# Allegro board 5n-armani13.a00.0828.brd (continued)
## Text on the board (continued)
BOTTOM: list("[Spacing] BOTTOM" "164.Shape to Route Keepin" "0 MIL [DEFAULT]" "0 MIL" "0.00 MIL" "DRC ERROR CLASS/BOTTOM" "[Shape] Route Keepin/All ((-191.01 273.9) (8699.38 4792.96))" "[Bottom Shape] GND ((-190.81 3053.41) (316.0 3564.87))" list(-170.750000 3410.250000) nil)@@@list("iris_chen" "2017/08/22 17:18:39" nil "P16C000357-PC" "5n-armani13.a00")@@@list("anson_lee" "2017/08/24 14:23:02" nil "P172000029-PC" "5n-armani13.a00.0824") | list("[Spacing] BOTTOM" "169.Shape to Route Keepin" "0 MIL [DEFAULT]" "0 MIL" "0.00 MIL" "DRC ERROR CLASS/BOTTOM" "[Shape] Route Keepin/All ((-191.01 273.9) (8699.38 4792.96))" "[Bottom Shape] GND ((-178.93 2335.01) (329.36 2652.0))" list(-106.990000 2480.120000) nil)@@@list("iris_chen" "2017/08/22 17:18:32" nil "P16C000357-PC" "5n-armani13.a00")@@@list("anson_lee" "2017/08/24 14:23:07" nil "P172000029-PC" "5n-armani13.a00.0824") | list("[Spacing] BOTTOM" "1.Shape to Route Keepout" "0 MIL [DEFAULT]" "0 MIL" "0.00 MIL" "DRC ERROR CLASS/BOTTOM" "[Shape] Route Keepout/Bottom ((-101.81 3966.17) (127.19 4181.63))" "[Bottom Shape] GND ((-191.01 273.9) (8699.38 4792.96))" list(-99.870000 3966.170000) nil)@@@list("iris_chen" "2017/08/24 17:08:49" nil "P16C000357-PC" "5n-armani13.a00")@@@list("jennifer_hsu" "2017/08/25 12:01:17" nil "p143000039-pc" "5n-armani13.a00") | list("[Spacing] BOTTOM" "3.Shape to Route Keepout" "0 MIL [DEFAULT]" "0 MIL" "0.00 MIL" "DRC ERROR CLASS/BOTTOM" "[Shape] Route Keepout/All ((-211.01 253.9) (8719.38 4812.96))" "[Bottom Shape] GND ((-90.47 1360.18) (215.46 1675.18))" list(-90.350000 1464.670000) nil)@@@list("iris_chen" "2017/08/22 17:18:35" nil "P16C000357-PC" "5n-armani13.a00")@@@list("anson_lee" "2017/08/24 14:34:02" nil "P172000029-PC" "5n-armani13.a00.0824") | list("[Spacing] BOTTOM" "2.Shape to Route Keepin" "0 MIL [DEFAULT]" "0 MIL" "0.00 MIL" "DRC ERROR CLASS/BOTTOM" "[Shape] Route Keepin/All ((-191.01 273.9) (8699.38 4792.96))" "[Bottom Shape] GND ((-90.47 1360.18) (215.46 1675.18))" list(-82.350000 1446.130000) nil)@@@list("iris_chen" "2017/08/22 17:18:34" nil "P16C000357-PC" "5n-armani13.a00")@@@list("anson_lee" "2017/08/24 14:34:01" nil "P172000029-PC" "5n-armani13.a00.0824") | list("[Spacing] BOTTOM" "179.Shape to Route Keepout" "0 MIL [DEFAULT]" "0 MIL" "0.00 MIL" "DRC ERROR CLASS/BOTTOM" "[Shape] Route Keepout/Bottom ((-109.54 1350.18) (225.46 1685.18))" "[Bottom Shape] GND ((-82.35 273.9) (8493.57 1710.0))" list(-82.350000 1426.200000) nil)@@@list("iris_chen" "2017/08/22 17:18:36" nil "P16C000357-PC" "5n-armani13.a00")@@@nil | list("[Spacing] BOTTOM" "167.Shape to Route Keepout" "0 MIL [DEFAULT]" "0 MIL" "0.00 MIL" "DRC ERROR CLASS/BOTTOM" "[Shape] Route Keepout/All ((-211.01 253.9) (8719.38 4812.96))" "[Bottom Shape] GND ((-24.57 3163.49) (207.43 3395.49))" list(-24.570000 3185.200000) nil)@@@list("iris_chen" "2017/08/22 17:18:33" nil "P16C000357-PC" "5n-armani13.a00")@@@list("anson_lee" "2017/08/24 14:23:05" nil "P172000029-PC" "5n-armani13.a00.0824") | list("[Spacing] BOTTOM" "168.Shape to Route Keepout" "0 MIL [DEFAULT]" "0 MIL" "0.00 MIL" "DRC ERROR CLASS/BOTTOM" "[Shape] Route Keepout/All ((-237.5 2495.83) (182.17 3240.31))" "[Bottom Shape] GND ((-24.57 3163.49) (207.43 3395.49))" list(-24.570000 3185.190000) nil)@@@list("iris_chen" "2017/08/22 17:18:33" nil "P16C000357-PC" "5n-armani13.a00")@@@list("anson_lee" "2017/08/24 14:23:06" nil "P172000029-PC" "5n-armani13.a00.0824") | list("[Spacing] BOTTOM" "181.Shape to Route Keepin" "0 MIL [DEFAULT]" "0 MIL" "0.00 MIL" "DRC ERROR CLASS/BOTTOM" "[Shape] Route Keepin/All ((-191.01 273.9) (8699.38 4792.96))" "[Bottom Shape] AGND ((-21.02 1889.86) (162.01 1960.27))" list(-2.240000 1932.020000) nil)@@@list("iris_chen" "2017/08/22 17:18:41" nil "P16C000357-PC" "5n-armani13.a00")@@@list("anson_lee" "2017/08/24 14:23:49" nil "P172000029-PC" "5n-armani13.a00.0824") | list("[Spacing] BOTTOM" "182.Thru Pin to Thru Pin" "5 MIL [(12)]" "4 MIL" "1.00 MIL" "DRC ERROR CLASS/BOTTOM" "[ThruPin] TX2N_P1_C (<uTiL>cId4355<uTiL>.B3) (12.89 3746.02)" "[ThruPin] TX2P_P1_C (<uTiL>cId4355<uTiL>.B2) (12.89 3777.52)" list(12.890000 3759.770000) nil)@@@list("iris_chen" "2017/08/22 17:18:41" nil "P16C000357-PC" "5n-armani13.a00")@@@list("anson_lee" "2017/08/24 14:23:50" nil "P172000029-PC" "5n-armani13.a00.0824") | list("[Spacing] BOTTOM" "165.Thru Pin to Thru Pin" "5 MIL [(12)]" "4 MIL" "1.00 MIL" "DRC ERROR CLASS/BOTTOM" "[ThruPin] RX1N_P1 (<uTiL>cId4355<uTiL>.B10) (12.89 3612.16)" "[ThruPin] RX1P_P1 (<uTiL>cId4355<uTiL>.B11) (12.89 3580.66)" list(12.890000 3598.410000) nil)@@@list("iris_chen" "2017/08/22 17:18:37" nil "P16C000357-PC" "5n-armani13.a00")@@@list("anson_lee" "2017/08/24 14:23:03" nil "P172000029-PC" "5n-armani13.a00.0824") | list("[Spacing] BOTTOM" "180.Thru Pin to Thru Pin" "5 MIL [(15)]" "4 MIL" "1.00 MIL" "DRC ERROR CLASS/BOTTOM" "[ThruPin] DN2 (<uTiL>cId4355<uTiL>.B7) (48.32 3663.34)" "[ThruPin] DP2 (<uTiL>cId4355<uTiL>.B6) (48.32 3694.84)" list(48.320000 3677.090000) nil)@@@list("iris_chen" "2017/08/22 17:18:38" nil "P16C000357-PC" "5n-armani13.a00")@@@list("anson_lee" "2017/08/24 14:23:48" nil "P172000029-PC" "5n-armani13.a00.0824") | list("[Spacing] BOTTOM" "179.Shape to Route Keepin" "0 MIL [DEFAULT]" "0 MIL" "0.00 MIL" "DRC ERROR CLASS/BOTTOM" "[Shape] Route Keepin/All ((-191.01 273.9) (8699.38 4792.96))" "[Bottom Shape] AGND ((26.54 2279.82) (160.9 2337.32))" list(49.770000 2282.580000) nil)@@@list("iris_chen" "2017/08/22 17:18:31" nil "P16C000357-PC" "5n-armani13.a00")@@@list("anson_lee" "2017/08/24 14:23:47" nil "P172000029-PC" "5n-armani13.a00.0824") | list("[Spacing] BOTTOM" "171.Shape to Route Keepout" "0 MIL [DEFAULT]" "0 MIL" "0.00 MIL" "DRC ERROR CLASS/BOTTOM" "[Shape] Route Keepout/Bottom ((-101.81 3966.17) (127.19 4181.63))" "[Bottom Shape] GND ((-191.01 273.9) (8699.38 4792.96))" list(64.170000 3966.170000) nil)@@@list("iris_chen" "2017/08/22 17:18:37" nil "P16C000357-PC" "5n-armani13.a00")@@@list("anson_lee" "2017/08/24 14:23:10" nil "P172000029-PC" "5n-armani13.a00.0824") | list("[Spacing] BOTTOM" "172.Drill Hole to Pin" "8 MIL [DEFAULT]" "7.99 MIL" "0.01 MIL" "DRC ERROR CLASS/BOTTOM" "[ThruPin] Dummy (<uTiL>cId4355<uTiL>.24) (93.01 3814.92)" "[SmdPin] GND (<uTiL>cId4355<uTiL>.A12) (90.65 3787.36)" list(98.230000 3800.860000) nil)@@@list("iris_chen" "2017/08/22 17:18:37" nil "P16C000357-PC" "5n-armani13.a00")@@@list("anson_lee" "2017/08/24 14:23:11" nil "P172000029-PC" "5n-armani13.a00.0824") | list("[Spacing] BOTTOM" "185.Drill Hole to Pin" "8 MIL [DEFAULT]" "7.99 MIL" "0.01 MIL" "DRC ERROR CLASS/BOTTOM" "[ThruPin] Dummy (<uTiL>cId4355<uTiL>.23) (93.01 3543.26)" "[SmdPin] GND (<uTiL>cId4355<uTiL>.A1) (90.65 3570.82)" list(98.230000 3557.320000) nil)@@@list("iris_chen" "2017/08/22 17:18:30" nil "P16C000357-PC" "5n-armani13.a00")@@@list("anson_lee" "2017/08/24 14:23:55" nil "P172000029-PC" "5n-armani13.a00.0824") | list("[Spacing] BOTTOM" "166.Shape to Route Keepin" "0 MIL [DEFAULT]" "0 MIL" "0.00 MIL" "DRC ERROR CLASS/BOTTOM" "[Shape] Route Keepin/All ((-191.01 273.9) (8699.38 4792.96))" "[Bottom Shape] GND ((-24.57 3163.49) (207.43 3395.49))" list(188.890000 3163.490000) nil)@@@list("iris_chen" "2017/08/22 17:18:32" nil "P16C000357-PC" "5n-armani13.a00")@@@list("anson_lee" "2017/08/24 14:23:04" nil "P172000029-PC" "5n-armani13.a00.0824") | list("[Physical] BOTTOM" "261.Pad/Pad Direct Connect" "NOT_ALLOWED [85OHM(DP_4|4.3|4|5/4/5/200)]" "ALL_ALLOWED" "" "DRC ERROR CLASS/BOTTOM" "[SmdPin] DN1 (<uTiL>cId1333<uTiL>.3) (354.17 3552.53)" "[SmdPin] DN1 (<uTiL>cId2437<uTiL>.4) (353.0 3544.0)" list(353.000000 3544.000000) nil)@@@list("iris_chen" "2017/08/22 17:19:52" nil "P16C000357-PC" "5n-armani13.a00")@@@list("anson_lee" "2017/08/24 14:24:52" nil "P172000029-PC" "5n-armani13.a00.0824") | list("[Physical] BOTTOM" "363.Pad/Pad Direct Connect" "NOT_ALLOWED [85OHM(DP_4|4.3|4|5/4/5/200)]" "ALL_ALLOWED" "" "DRC ERROR CLASS/BOTTOM" "[SmdPin] DN1_MUX (<uTiL>cId1333<uTiL>.4) (354.17 3493.47)" "[SmdPin] DN1_MUX (<uTiL>cId2437<uTiL>.3) (353.0 3502.0)" list(353.000000 3502.000000) nil)@@@list("iris_chen" "2017/08/22 17:19:39" nil "P16C000357-PC" "5n-armani13.a00")@@@list("anson_lee" "2017/08/24 14:26:01" nil "P172000029-PC" "5n-armani13.a00.0824") | list("[Physical] BOTTOM" "386.Pad/Pad Direct Connect" "NOT_ALLOWED [85OHM(DP_4|4.3|4|5/4/5/200)]" "ALL_ALLOWED" "" "DRC ERROR CLASS/BOTTOM" "[SmdPin] DP1_MUX (<uTiL>cId2437<uTiL>.1) (377.0 3502.0)" "[SmdPin] DP1_MUX (<uTiL>cId1333<uTiL>.1) (375.83 3493.47)" list(375.830000 3493.470000) nil)@@@list("iris_chen" "2017/08/22 17:21:12" nil "P16C000357-PC" "5n-armani13.a00")@@@list("anson_lee" "2017/08/24 14:26:15" nil "P172000029-PC" "5n-armani13.a00.0824") | list("[Physical] BOTTOM" "273.Pad/Pad Direct Connect" "NOT_ALLOWED [85OHM(DP_4|4.3|4|5/4/5/200)]" "ALL_ALLOWED" "" "DRC ERROR CLASS/BOTTOM" "[SmdPin] DP1 (<uTiL>cId1333<uTiL>.2) (375.83 3552.53)" "[SmdPin] DP1 (<uTiL>cId2437<uTiL>.2) (377.0 3544.0)" list(377.000000 3544.000000) nil)@@@list("iris_chen" "2017/08/22 17:19:12" nil "P16C000357-PC" "5n-armani13.a00")@@@list("anson_lee" "2017/08/24 14:24:59" nil "P172000029-PC" "5n-armani13.a00.0824") | list("[Physical] BOTTOM" "337.Pad/Pad Direct Connect" "NOT_ALLOWED [(GND_20)]" "ALL_ALLOWED" "" "DRC ERROR CLASS/BOTTOM" "[SmdPin] GND (<uTiL>cId30<uTiL>.49) (460.0 1405.0)" "[ThruPin] GND (<uTiL>cId30<uTiL>.50) (380.5 1484.5)" list(380.500000 1484.500000) nil)@@@list("iris_chen" "2017/08/22 17:21:11" nil "P16C000357-PC" "5n-armani13.a00")@@@list("anson_lee" "2017/08/24 14:25:43" nil "P172000029-PC" "5n-armani13.a00.0824") | list("[Physical] BOTTOM" "332.Pad/Pad Direct Connect" "NOT_ALLOWED [(GND_20)]" "ALL_ALLOWED" "" "DRC ERROR CLASS/BOTTOM" "[SmdPin] GND (<uTiL>cId30<uTiL>.49) (460.0 1405.0)" "[ThruPin] GND (<uTiL>cId30<uTiL>.51) (380.5 1405.0)" list(380.500000 1405.000000) nil)@@@list("iris_chen" "2017/08/22 17:19:50" nil "P16C000357-PC" "5n-armani13.a00")@@@list("anson_lee" "2017/08/24 14:25:40" nil "P172000029-PC" "5n-armani13.a00.0824") | list("[Physical] BOTTOM" "331.Pad/Pad Direct Connect" "NOT_ALLOWED [(GND_20)]" "ALL_ALLOWED" "" "DRC ERROR CLASS/BOTTOM" "[SmdPin] GND (<uTiL>cId30<uTiL>.49) (460.0 1405.0)" "[ThruPin] GND (<uTiL>cId30<uTiL>.52) (380.5 1325.5)" list(380.500000 1325.500000) nil)@@@list("iris_chen" "2017/08/22 17:19:50" nil "P16C000357-PC" "5n-armani13.a00")@@@list("anson_lee" "2017/08/24 14:25:39" nil "P172000029-PC" "5n-armani13.a00.0824") | list("[Physical] BOTTOM" "257.Pad/Pad Direct Connect" "NOT_ALLOWED [85OHM(DP_4|4.3|4|5/4/5/200)]" "ALL_ALLOWED" "" "DRC ERROR CLASS/BOTTOM" "[SmdPin] HDMI_TMDS_CLK_N (<uTiL>cId4643<uTiL>.2) (430.0 2901.0)" "[SmdPin] HDMI_TMDS_CLK_N (<uTiL>cId2614<uTiL>.4) (420.47 2899.83)" list(420.470000 2899.830000) nil)@@@list("iris_chen" "2017/08/22 17:19:14" nil "P16C000357-PC" "5n-armani13.a00")@@@list("anson_lee" "2017/08/24 14:24:50" nil "P172000029-PC" "5n-armani13.a00.0824") | list("[Physical] BOTTOM" "265.Pad/Pad Direct Connect" "NOT_ALLOWED [85OHM(DP_4|4.3|4|5/4/5/200)]" "ALL_ALLOWED" "" "DRC ERROR CLASS/BOTTOM" "[SmdPin] HDMI_TMDS_CLK_P (<uTiL>cId4643<uTiL>.4) (430.0 2877.0)" "[SmdPin] HDMI_TMDS_CLK_P (<uTiL>cId2614<uTiL>.1) (420.47 2878.17)" list(420.470000 2878.170000) nil)@@@list("iris_chen" "2017/08/22 17:19:12" nil "P16C000357-PC" "5n-armani13.a00")@@@list("anson_lee" "2017/08/24 14:24:54" nil "P172000029-PC" "5n-armani13.a00.0824") | list("[Physical] BOTTOM" "254.Pad/Pad Direct Connect" "NOT_ALLOWED [85OHM(DP_4|4.3|4|5/4/5/200)]" "ALL_ALLOWED" "" "DRC ERROR CLASS/BOTTOM" "[SmdPin] HDMI_TMDS_DATA1_N (<uTiL>cId4645<uTiL>.2) (429.0 2727.0)" "[SmdPin] HDMI_TMDS_DATA1_N (<uTiL>cId2616<uTiL>.4) (420.47 2726.83)" list(420.470000 2726.830000) nil)@@@list("iris_chen" "2017/08/22 17:19:36" nil "P16C000357-PC" "5n-armani13.a00")@@@list("anson_lee" "2017/08/24 14:24:48" nil "P172000029-PC" "5n-armani13.a00.0824") | list("[Physical] BOTTOM" "382.Pad/Pad Direct Connect" "NOT_ALLOWED [85OHM(DP_4|4.3|4|5/4/5/200)]" "ALL_ALLOWED" "" "DRC ERROR CLASS/BOTTOM" "[SmdPin] HDMI_TMDS_DATA2_N (<uTiL>cId4644<uTiL>.2) (429.0 2637.0)" "[SmdPin] HDMI_TMDS_DATA2_N (<uTiL>cId2615<uTiL>.4) (420.47 2635.83)" list(420.470000 2635.830000) nil)@@@list("iris_chen" "2017/08/22 17:19:13" nil "P16C000357-PC" "5n-armani13.a00")@@@list("anson_lee" "2017/08/24 14:26:13" nil "P172000029-PC" "5n-armani13.a00.0824") | list("[Physical] BOTTOM" "268.Pad/Pad Direct Connect" "NOT_ALLOWED [85OHM(DP_4|4.3|4|5/4/5/200)]" "ALL_ALLOWED" "" "DRC ERROR CLASS/BOTTOM" "[SmdPin] HDMI_TMDS_DATA0_N (<uTiL>cId4646<uTiL>.2) (430.0 2811.0)" "[SmdPin] HDMI_TMDS_DATA0_N (<uTiL>cId2617<uTiL>.4) (421.47 2809.83)" list(421.470000 2809.830000) nil)@@@list("iris_chen" "2017/08/22 17:19:56" nil "P16C000357-PC" "5n-armani13.a00")@@@list("anson_lee" "2017/08/24 14:24:56" nil "P172000029-PC" "5n-armani13.a00.0824") | list("[Physical] BOTTOM" "253.Pad/Pad Direct Connect" "NOT_ALLOWED [85OHM(DP_4|4.3|4|5/4/5/200)]" "ALL_ALLOWED" "" "DRC ERROR CLASS/BOTTOM" "[SmdPin] HDMI_TMDS_DATA1_P (<uTiL>cId2616<uTiL>.1) (420.47 2705.17)" "[SmdPin] HDMI_TMDS_DATA1_P (<uTiL>cId4645<uTiL>.4) (429.0 2703.0)" list(429.000000 2703.000000) nil)@@@list("iris_chen" "2017/08/22 17:21:12" nil "P16C000357-PC" "5n-armani13.a00")@@@list("anson_lee" "2017/08/24 14:24:47" nil "P172000029-PC" "5n-armani13.a00.0824") | list("[Physical] BOTTOM" "272.Pad/Pad Direct Connect" "NOT_ALLOWED [85OHM(DP_4|4.3|4|5/4/5/200)]" "ALL_ALLOWED" "" "DRC ERROR CLASS/BOTTOM" "[SmdPin] HDMI_TMDS_DATA2_P (<uTiL>cId2615<uTiL>.1) (420.47 2614.17)" "[SmdPin] HDMI_TMDS_DATA2_P (<uTiL>cId4644<uTiL>.4) (429.0 2613.0)" list(429.000000 2613.000000) nil)@@@list("iris_chen" "2017/08/22 17:19:36" nil "P16C000357-PC" "5n-armani13.a00")@@@list("anson_lee" "2017/08/24 14:24:59" nil "P172000029-PC" "5n-armani13.a00.0824") | list("[Physical] BOTTOM" "252.Pad/Pad Direct Connect" "NOT_ALLOWED [85OHM(DP_4|4.3|4|5/4/5/200)]" "ALL_ALLOWED" "" "DRC ERROR CLASS/BOTTOM" "[SmdPin] HDMI_TMDS_DATA0_P (<uTiL>cId2617<uTiL>.1) (421.47 2788.17)" "[SmdPin] HDMI_TMDS_DATA0_P (<uTiL>cId4646<uTiL>.4) (430.0 2787.0)" list(430.000000 2787.000000) nil)@@@list("iris_chen" "2017/08/22 17:19:45" nil "P16C000357-PC" "5n-armani13.a00")@@@list("anson_lee" "2017/08/24 14:24:46" nil "P172000029-PC" "5n-armani13.a00.0824") | list("[Physical] BOTTOM" "388.Pad/Pad Direct Connect" "NOT_ALLOWED [DEFAULT]" "ALL_ALLOWED" "" "DRC ERROR CLASS/BOTTOM" "[ThruPin] PRO_THM (<uTiL>cId6387<uTiL>.19) (455.47 3890.81)" "[SmdPin] PRO_THM (<uTiL>cId6387<uTiL>.18) (485.0 3851.44)" list(455.470000 3890.810000) nil)@@@list("iris_chen" "2017/08/22 17:19:25" nil "P16C000357-PC" "5n-armani13.a00")@@@list("anson_lee" "2017/08/24 14:26:16" nil "P172000029-PC" "5n-armani13.a00.0824") | list("[Physical] BOTTOM" "394.Pad/Pad Direct Connect" "NOT_ALLOWED [DEFAULT]" "ALL_ALLOWED" "" "DRC ERROR CLASS/BOTTOM" "[ThruPin] PRO_THM (<uTiL>cId6387<uTiL>.20) (455.47 3851.44)" "[SmdPin] PRO_THM (<uTiL>cId6387<uTiL>.18) (485.0 3851.44)" list(455.470000 3851.440000) nil)@@@list("iris_chen" "2017/08/22 17:21:09" nil "P16C000357-PC" "5n-armani13.a00")@@@list("anson_lee" "2017/08/24 14:26:21" nil "P172000029-PC" "5n-armani13.a00.0824") | list("[Physical] BOTTOM" "393.Pad/Pad Direct Connect" "NOT_ALLOWED [DEFAULT]" "ALL_ALLOWED" "" "DRC ERROR CLASS/BOTTOM" "[ThruPin] PRO_THM (<uTiL>cId6387<uTiL>.21) (455.47 3812.07)" "[SmdPin] PRO_THM (<uTiL>cId6387<uTiL>.18) (485.0 3851.44)" list(455.470000 3812.070000) nil)@@@list("iris_chen" "2017/08/22 17:19:26" nil "P16C000357-PC" "5n-armani13.a00")@@@list("anson_lee" "2017/08/24 14:26:20" nil "P172000029-PC" "5n-armani13.a00.0824") | list("[Physical] BOTTOM" "283.Pad/Pad Direct Connect" "NOT_ALLOWED [(GND_20)]" "ALL_ALLOWED" "" "DRC ERROR CLASS/BOTTOM" "[SmdPin] GND (<uTiL>cId30<uTiL>.49) (460.0 1405.0)" "[ThruPin] GND (<uTiL>cId30<uTiL>.53) (460.0 1484.5)" list(460.000000 1484.500000) nil)@@@list("iris_chen" "2017/08/22 17:19:51" nil "P16C000357-PC" "5n-armani13.a00")@@@list("anson_lee" "2017/08/24 14:25:05" nil "P172000029-PC" "5n-armani13.a00.0824") | list("[Physical] BOTTOM" "333.Pad/Pad Direct Connect" "NOT_ALLOWED [(GND_20)]" "ALL_ALLOWED" "" "DRC ERROR CLASS/BOTTOM" "[SmdPin] GND (<uTiL>cId30<uTiL>.49) (460.0 1405.0)" "[ThruPin] GND (<uTiL>cId30<uTiL>.54) (460.0 1405.0)" list(460.000000 1405.000000) nil)@@@list("iris_chen" "2017/08/22 17:19:49" nil "P16C000357-PC" "5n-armani13.a00")@@@list("anson_lee" "2017/08/24 14:25:40" nil "P172000029-PC" "5n-armani13.a00.0824") | list("[Physical] BOTTOM" "334.Pad/Pad Direct Connect" "NOT_ALLOWED [(GND_20)]" "ALL_ALLOWED" "" "DRC ERROR CLASS/BOTTOM" "[SmdPin] GND (<uTiL>cId30<uTiL>.49) (460.0 1405.0)" "[ThruPin] GND (<uTiL>cId30<uTiL>.55) (460.0 1325.5)" list(460.000000 1325.500000) nil)@@@list("iris_chen" "2017/08/22 17:19:49" nil "P16C000357-PC" "5n-armani13.a00")@@@list("anson_lee" "2017/08/24 14:25:41" nil "P172000029-PC" "5n-armani13.a00.0824") | list("[Physical] BOTTOM" "349.Pad/Pad Direct Connect" "NOT_ALLOWED [(GND_20)]" "ALL_ALLOWED" "" "DRC ERROR CLASS/BOTTOM" "[SmdPin] GND (<uTiL>cId2509<uTiL>.21) (485.0 3419.0)" "[ThruPin] GND (<uTiL>cId2509<uTiL>.25) (465.31 3438.69)" list(465.310000 3438.690000) nil)@@@list("iris_chen" "2017/08/22 17:19:46" nil "P16C000357-PC" "5n-armani13.a00")@@@list("anson_lee" "2017/08/24 14:25:52" nil "P172000029-PC" "5n-armani13.a00.0824") | list("[Physical] BOTTOM" "348.Pad/Pad Direct Connect" "NOT_ALLOWED [(GND_20)]" "ALL_ALLOWED" "" "DRC ERROR CLASS/BOTTOM" "[SmdPin] GND (<uTiL>cId2509<uTiL>.21) (485.0 3419.0)" "[ThruPin] GND (<uTiL>cId2509<uTiL>.22) (465.31 3399.31)" list(465.310000 3399.310000) nil)@@@list("iris_chen" "2017/08/22 17:19:24" nil "P16C000357-PC" "5n-armani13.a00")@@@list("anson_lee" "2017/08/24 14:25:51" nil "P172000029-PC" "5n-armani13.a00.0824") | list("[Physical] BOTTOM" "258.Pad/Pad Direct Connect" "NOT_ALLOWED [85OHM(DP_4|4.3|4|5/4/5/200)]" "ALL_ALLOWED" "" "DRC ERROR CLASS/BOTTOM" "[SmdPin] HDMI_TXP1_SNK (<uTiL>cId2616<uTiL>.2) (479.53 2705.17)" "[SmdPin] HDMI_TXP1_SNK (<uTiL>cId4645<uTiL>.3) (471.0 2703.0)" list(471.000000 2703.000000) nil)@@@list("iris_chen" "2017/08/22 17:19:56" nil "P16C000357-PC" "5n-armani13.a00")@@@list("anson_lee" "2017/08/24 14:24:50" nil "P172000029-PC" "5n-armani13.a00.0824") | list("[Physical] BOTTOM" "278.Pad/Pad Direct Connect" "NOT_ALLOWED [85OHM(DP_4|4.3|4|5/4/5/200)]" "ALL_ALLOWED" "" "DRC ERROR CLASS/BOTTOM" "[SmdPin] HDMI_TXN2_SNK (<uTiL>cId2615<uTiL>.3) (479.53 2635.83)" "[SmdPin] HDMI_TXN2_SNK (<uTiL>cId4644<uTiL>.1) (471.0 2637.0)" list(471.000000 2637.000000) nil)@@@list("iris_chen" "2017/08/22 17:19:57" nil "P16C000357-PC" "5n-armani13.a00")@@@list("anson_lee" "2017/08/24 14:25:02" nil "P172000029-PC" "5n-armani13.a00.0824") | list("[Physical] BOTTOM" "361.Pad/Pad Direct Connect" "NOT_ALLOWED [85OHM(DP_4|4.3|4|5/4/5/200)]" "ALL_ALLOWED" "" "DRC ERROR CLASS/BOTTOM" "[SmdPin] HDMI_CLKN_SNK (<uTiL>cId2614<uTiL>.3) (479.53 2899.83)" "[SmdPin] HDMI_CLKN_SNK (<uTiL>cId4643<uTiL>.1) (472.0 2901.0)" list(472.000000 2901.000000) nil)@@@list("iris_chen" "2017/08/22 17:21:19" nil "P16C000357-PC" "5n-armani13.a00")@@@list("anson_lee" "2017/08/24 14:25:59" nil "P172000029-PC" "5n-armani13.a00.0824") | list("[Physical] BOTTOM" "362.Pad/Pad Direct Connect" "NOT_ALLOWED [85OHM(DP_4|4.3|4|5/4/5/200)]" "ALL_ALLOWED" "" "DRC ERROR CLASS/BOTTOM" "[SmdPin] HDMI_TXN0_SNK (<uTiL>cId2617<uTiL>.3) (480.53 2809.83)" "[SmdPin] HDMI_TXN0_SNK (<uTiL>cId4646<uTiL>.1) (472.0 2811.0)" list(472.000000 2811.000000) nil)@@@list("iris_chen" "2017/08/22 17:21:19" nil "P16C000357-PC" "5n-armani13.a00")@@@list("anson_lee" "2017/08/24 14:26:00" nil "P172000029-PC" "5n-armani13.a00.0824") | list("[Physical] BOTTOM" "383.Pad/Pad Direct Connect" "NOT_ALLOWED [85OHM(DP_4|4.3|4|5/4/5/200)]" "ALL_ALLOWED" "" "DRC ERROR CLASS/BOTTOM" "[SmdPin] HDMI_CLKP_SNK (<uTiL>cId4643<uTiL>.3) (472.0 2877.0)" "[SmdPin] HDMI_CLKP_SNK (<uTiL>cId2614<uTiL>.2) (479.53 2878.17)" list(479.530000 2878.170000) nil)@@@list("iris_chen" "2017/08/22 17:19:51" nil "P16C000357-PC" "5n-armani13.a00")@@@list("anson_lee" "2017/08/24 14:26:13" nil "P172000029-PC" "5n-armani13.a00.0824") | list("[Physical] BOTTOM" "259.Pad/Pad Direct Connect" "NOT_ALLOWED [85OHM(DP_4|4.3|4|5/4/5/200)]" "ALL_ALLOWED" "" "DRC ERROR CLASS/BOTTOM" "[SmdPin] HDMI_TXN1_SNK (<uTiL>cId4645<uTiL>.1) (471.0 2727.0)" "[SmdPin] HDMI_TXN1_SNK (<uTiL>cId2616<uTiL>.3) (479.53 2726.83)" list(479.530000 2726.830000) nil)@@@list("iris_chen" "2017/08/22 17:19:28" nil "P16C000357-PC" "5n-armani13.a00")@@@list("anson_lee" "2017/08/24 14:24:51" nil "P172000029-PC" "5n-armani13.a00.0824") | list("[Physical] BOTTOM" "269.Pad/Pad Direct Connect" "NOT_ALLOWED [85OHM(DP_4|4.3|4|5/4/5/200)]" "ALL_ALLOWED" "" "DRC ERROR CLASS/BOTTOM" "[SmdPin] HDMI_TXP2_SNK (<uTiL>cId4644<uTiL>.3) (471.0 2613.0)" "[SmdPin] HDMI_TXP2_SNK (<uTiL>cId2615<uTiL>.2) (479.53 2614.17)" list(479.530000 2614.170000) nil)@@@list("iris_chen" "2017/08/22 17:19:52" nil "P16C000357-PC" "5n-armani13.a00")@@@list("anson_lee" "2017/08/24 14:24:57" nil "P172000029-PC" "5n-armani13.a00.0824") | list("[Physical] BOTTOM" "255.Pad/Pad Direct Connect" "NOT_ALLOWED [85OHM(DP_4|4.3|4|5/4/5/200)]" "ALL_ALLOWED" "" "DRC ERROR CLASS/BOTTOM" "[SmdPin] HDMI_TXP0_SNK (<uTiL>cId4646<uTiL>.3) (472.0 2787.0)" "[SmdPin] HDMI_TXP0_SNK (<uTiL>cId2617<uTiL>.2) (480.53 2788.17)" list(480.530000 2788.170000) nil)@@@list("iris_chen" "2017/08/22 17:19:27" nil "P16C000357-PC" "5n-armani13.a00")@@@list("anson_lee" "2017/08/24 14:24:48" nil "P172000029-PC" "5n-armani13.a00.0824") | list("[Physical] BOTTOM" "392.Pad/Pad Direct Connect" "NOT_ALLOWED [DEFAULT]" "ALL_ALLOWED" "" "DRC ERROR CLASS/BOTTOM" "[ThruPin] PRO_THM (<uTiL>cId6387<uTiL>.22) (485.0 3871.13)" "[SmdPin] PRO_THM (<uTiL>cId6387<uTiL>.18) (485.0 3851.44)" list(485.000000 3871.130000) nil)@@@list("iris_chen" "2017/08/22 17:19:36" nil "P16C000357-PC" "5n-armani13.a00")@@@list("anson_lee" "2017/08/24 14:26:19" nil "P172000029-PC" "5n-armani13.a00.0824") | list("[Physical] BOTTOM" "391.Pad/Pad Direct Connect" "NOT_ALLOWED [DEFAULT]" "ALL_ALLOWED" "" "DRC ERROR CLASS/BOTTOM" "[ThruPin] PRO_THM (<uTiL>cId6387<uTiL>.23) (485.0 3831.76)" "[SmdPin] PRO_THM (<uTiL>cId6387<uTiL>.18) (485.0 3851.44)" list(485.000000 3831.760000) nil)@@@list("iris_chen" "2017/08/22 17:19:46" nil "P16C000357-PC" "5n-armani13.a00")@@@list("anson_lee" "2017/08/24 14:26:18" nil "P172000029-PC" "5n-armani13.a00.0824") | list("[Physical] BOTTOM" "345.Pad/Pad Direct Connect" "NOT_ALLOWED [(GND_20)]" "ALL_ALLOWED" "" "DRC ERROR CLASS/BOTTOM" "[SmdPin] GND (<uTiL>cId2509<uTiL>.21) (485.0 3419.0)" "[ThruPin] GND (<uTiL>cId2509<uTiL>.24) (485.0 3419.0)" list(485.000000 3419.000000) nil)@@@list("iris_chen" "2017/08/22 17:19:24" nil "P16C000357-PC" "5n-armani13.a00")@@@list("anson_lee" "2017/08/24 14:25:48" nil "P172000029-PC" "5n-armani13.a00.0824") | list("[Physical] BOTTOM" "346.Pad/Pad Direct Connect" "NOT_ALLOWED [(GND_20)]" "ALL_ALLOWED" "" "DRC ERROR CLASS/BOTTOM" "[SmdPin] GND (<uTiL>cId2509<uTiL>.21) (485.0 3419.0)" "[ThruPin] GND (<uTiL>cId2509<uTiL>.26) (504.69 3438.69)" list(504.690000 3438.690000) nil)@@@list("iris_chen" "2017/08/22 17:19:37" nil "P16C000357-PC" "5n-armani13.a00")@@@list("anson_lee" "2017/08/24 14:25:49" nil "P172000029-PC" "5n-armani13.a00.0824") | list("[Physical] BOTTOM" "282.Pad/Pad Direct Connect" "NOT_ALLOWED [(GND_20)]" "ALL_ALLOWED" "" "DRC ERROR CLASS/BOTTOM" "[SmdPin] GND (<uTiL>cId2509<uTiL>.21) (485.0 3419.0)" "[ThruPin] GND (<uTiL>cId2509<uTiL>.23) (504.69 3399.31)" list(504.690000 3399.310000) nil)@@@list("iris_chen" "2017/08/22 17:21:10" nil "P16C000357-PC" "5n-armani13.a00")@@@list("anson_lee" "2017/08/24 14:25:04" nil "P172000029-PC" "5n-armani13.a00.0824") | list("[Physical] BOTTOM" "387.Pad/Pad Direct Connect" "NOT_ALLOWED [DEFAULT]" "ALL_ALLOWED" "" "DRC ERROR CLASS/BOTTOM" "[ThruPin] PRO_THM (<uTiL>cId6387<uTiL>.24) (514.53 3890.81)" "[SmdPin] PRO_THM (<uTiL>cId6387<uTiL>.18) (485.0 3851.44)" list(514.530000 3890.810000) nil)@@@list("iris_chen" "2017/08/22 17:21:09" nil "P16C000357-PC" "5n-armani13.a00")@@@list("anson_lee" "2017/08/24 14:26:16" nil "P172000029-PC" "5n-armani13.a00.0824") | list("[Physical] BOTTOM" "390.Pad/Pad Direct Connect" "NOT_ALLOWED [DEFAULT]" "ALL_ALLOWED" "" "DRC ERROR CLASS/BOTTOM" "[ThruPin] PRO_THM (<uTiL>cId6387<uTiL>.25) (514.53 3851.44)" "[SmdPin] PRO_THM (<uTiL>cId6387<uTiL>.18) (485.0 3851.44)" list(514.530000 3851.440000) nil)@@@list("iris_chen" "2017/08/22 17:19:26" nil "P16C000357-PC" "5n-armani13.a00")@@@list("anson_lee" "2017/08/24 14:26:18" nil "P172000029-PC" "5n-armani13.a00.0824") | list("[Physical] BOTTOM" "389.Pad/Pad Direct Connect" "NOT_ALLOWED [DEFAULT]" "ALL_ALLOWED" "" "DRC ERROR CLASS/BOTTOM" "[ThruPin] PRO_THM (<uTiL>cId6387<uTiL>.26) (514.53 3812.07)" "[SmdPin] PRO_THM (<uTiL>cId6387<uTiL>.18) (485.0 3851.44)" list(514.530000 3812.070000) nil)@@@list("iris_chen" "2017/08/22 17:19:25" nil "P16C000357-PC" "5n-armani13.a00")@@@list("anson_lee" "2017/08/24 14:26:17" nil "P172000029-PC" "5n-armani13.a00.0824") | list("[Physical] BOTTOM" "335.Pad/Pad Direct Connect" "NOT_ALLOWED [(GND_20)]" "ALL_ALLOWED" "" "DRC ERROR CLASS/BOTTOM" "[SmdPin] GND (<uTiL>cId30<uTiL>.49) (460.0 1405.0)" "[ThruPin] GND (<uTiL>cId30<uTiL>.56) (539.5 1484.5)" list(539.500000 1484.500000) nil)@@@list("iris_chen" "2017/08/22 17:19:48" nil "P16C000357-PC" "5n-armani13.a00")@@@list("anson_lee" "2017/08/24 14:25:42" nil "P172000029-PC" "5n-armani13.a00.0824") | list("[Physical] BOTTOM" "352.Pad/Pad Direct Connect" "NOT_ALLOWED [(GND_20)]" "ALL_ALLOWED" "" "DRC ERROR CLASS/BOTTOM" "[SmdPin] GND (<uTiL>cId30<uTiL>.49) (460.0 1405.0)" "[ThruPin] GND (<uTiL>cId30<uTiL>.57) (539.5 1405.0)" list(539.500000 1405.000000) nil)@@@list("iris_chen" "2017/08/22 17:19:48" nil "P16C000357-PC" "5n-armani13.a00")@@@list("anson_lee" "2017/08/24 14:25:54" nil "P172000029-PC" "5n-armani13.a00.0824") | list("[Physical] BOTTOM" "336.Pad/Pad Direct Connect" "NOT_ALLOWED [(GND_20)]" "ALL_ALLOWED" "" "DRC ERROR CLASS/BOTTOM" "[SmdPin] GND (<uTiL>cId30<uTiL>.49) (460.0 1405.0)" "[ThruPin] GND (<uTiL>cId30<uTiL>.58) (539.5 1325.5)" list(539.500000 1325.500000) nil)@@@list("iris_chen" "2017/08/22 17:19:47" nil "P16C000357-PC" "5n-armani13.a00")@@@list("anson_lee" "2017/08/24 14:25:42" nil "P172000029-PC" "5n-armani13.a00.0824") | list("[Physical] BOTTOM" "291.Pad/Pad Direct Connect" "NOT_ALLOWED [(GND_20)]" "ALL_ALLOWED" "" "DRC ERROR CLASS/BOTTOM" "[SmdPin] GND (<uTiL>cId2761<uTiL>.11) (1556.0 870.0)" "[ThruPin] GND (<uTiL>cId2761<uTiL>.12) (1535.0 910.0)" list(1535.000000 910.000000) nil)@@@list("iris_chen" "2017/08/22 17:21:16" nil "P16C000357-PC" "5n-armani13.a00")@@@list("anson_lee" "2017/08/24 14:25:11" nil "P172000029-PC" "5n-armani13.a00.0824") | list("[Physical] BOTTOM" "289.Pad/Pad Direct Connect" "NOT_ALLOWED [(GND_20)]" "ALL_ALLOWED" "" "DRC ERROR CLASS/BOTTOM" "[ThruPin] GND (<uTiL>cId2761<uTiL>.13) (1535.0 830.0)" "[SmdPin] GND (<uTiL>cId2761<uTiL>.11) (1556.0 870.0)" list(1535.000000 830.000000) nil)@@@list("iris_chen" "2017/08/22 17:21:17" nil "P16C000357-PC" "5n-armani13.a00")@@@list("anson_lee" "2017/08/24 14:25:10" nil "P172000029-PC" "5n-armani13.a00.0824") | list("[Physical] BOTTOM" "292.Pad/Pad Direct Connect" "NOT_ALLOWED [(GND_20)]" "ALL_ALLOWED" "" "DRC ERROR CLASS/BOTTOM" "[SmdPin] GND (<uTiL>cId2761<uTiL>.11) (1556.0 870.0)" "[ThruPin] GND (<uTiL>cId2761<uTiL>.14) (1577.0 910.0)" list(1577.000000 910.000000) nil)@@@list("iris_chen" "2017/08/22 17:21:15" nil "P16C000357-PC" "5n-armani13.a00")@@@list("anson_lee" "2017/08/24 14:25:12" nil "P172000029-PC" "5n-armani13.a00.0824") | list("[Physical] BOTTOM" "290.Pad/Pad Direct Connect" "NOT_ALLOWED [(GND_20)]" "ALL_ALLOWED" "" "DRC ERROR CLASS/BOTTOM" "[SmdPin] GND (<uTiL>cId2761<uTiL>.11) (1556.0 870.0)" "[ThruPin] GND (<uTiL>cId2761<uTiL>.15) (1577.0 830.0)" list(1577.000000 830.000000) nil)@@@list("iris_chen" "2017/08/22 17:21:16" nil "P16C000357-PC" "5n-armani13.a00")@@@list("anson_lee" "2017/08/24 14:25:10" nil "P172000029-PC" "5n-armani13.a00.0824") | list("[Physical] BOTTOM" "250.Pad/Pad Direct Connect" "NOT_ALLOWED [85OHM(DP_4|4.3|4|5/4/5/200)]" "ALL_ALLOWED" "" "DRC ERROR CLASS/BOTTOM" "[SmdPin] USBN5_CAM (<uTiL>cId3444<uTiL>.2) (1859.47 4143.83)" "[SmdPin] USBN5_CAM (<uTiL>cId3529<uTiL>.3) (1868.0 4145.0)" list(1868.000000 4145.000000) nil)@@@list("iris_chen" "2017/08/22 17:21:24" nil "P16C000357-PC" "5n-armani13.a00")@@@list("anson_lee" "2017/08/24 14:24:45" nil "P172000029-PC" "5n-armani13.a00.0824") | list("[Physical] BOTTOM" "384.Pad/Pad Direct Connect" "NOT_ALLOWED [85OHM(DP_4|4.3|4|5/4/5/200)]" "ALL_ALLOWED" "" "DRC ERROR CLASS/BOTTOM" "[SmdPin] USBP5_CAM (<uTiL>cId3444<uTiL>.3) (1859.47 4122.17)" "[SmdPin] USBP5_CAM (<uTiL>cId3529<uTiL>.1) (1868.0 4121.0)" list(1868.000000 4121.000000) nil)@@@list("iris_chen" "2017/08/22 17:19:13" nil "P16C000357-PC" "5n-armani13.a00")@@@list("anson_lee" "2017/08/24 14:26:14" nil "P172000029-PC" "5n-armani13.a00.0824") | list("[Physical] BOTTOM" "385.Pad/Pad Direct Connect" "NOT_ALLOWED [85OHM(DP_4|4.3|4|5/4/5/200)]" "ALL_ALLOWED" "" "DRC ERROR CLASS/BOTTOM" "[SmdPin] USBP5+_CAM (<uTiL>cId3444<uTiL>.4) (1918.53 4122.17)" "[SmdPin] USBP5+_CAM (<uTiL>cId3529<uTiL>.2) (1910.0 4121.0)" list(1910.000000 4121.000000) nil)@@@list("iris_chen" "2017/08/22 17:21:24" nil "P16C000357-PC" "5n-armani13.a00")@@@list("anson_lee" "2017/08/24 14:26:15" nil "P172000029-PC" "5n-armani13.a00.0824") | list("[Physical] BOTTOM" "248.Pad/Pad Direct Connect" "NOT_ALLOWED [85OHM(DP_4|4.3|4|5/4/5/200)]" "ALL_ALLOWED" "" "DRC ERROR CLASS/BOTTOM" "[SmdPin] USBP5-_CAM (<uTiL>cId3529<uTiL>.4) (1910.0 4145.0)" "[SmdPin] USBP5-_CAM (<uTiL>cId3444<uTiL>.1) (1918.53 4143.83)" list(1918.530000 4143.830000) nil)@@@list("iris_chen" "2017/08/22 17:21:11" nil "P16C000357-PC" "5n-armani13.a00")@@@list("anson_lee" "2017/08/24 14:24:44" nil "P172000029-PC" "5n-armani13.a00.0824") | list("[Physical] BOTTOM" "270.Pad/Pad Direct Connect" "NOT_ALLOWED [DEFAULT]" "ALL_ALLOWED" "" "DRC ERROR CLASS/BOTTOM" "[SmdPin] +1P2V_DUAL_FB_VOUT_R_A (<uTiL>cId1150<uTiL>.2) (3549.0 4431.0)" "[SmdPin] +1P2V_DUAL_FB_VOUT_R_A (<uTiL>cId1170<uTiL>.1) (3513.46 4431.0)" list(3549.000000 4431.000000) nil)@@@list("iris_chen" "2017/08/22 17:19:58" nil "P16C000357-PC" "5n-armani13.a00")@@@list("anson_lee" "2017/08/24 14:24:57" nil "P172000029-PC" "5n-armani13.a00.0824") | list("[Physical] BOTTOM" "274.Pad/Pad Direct Connect" "NOT_ALLOWED [(PWR_20)]" "ALL_ALLOWED" "" "DRC ERROR CLASS/BOTTOM" "[SmdPin] +1P8VSB_OUT (<uTiL>cId1220<uTiL>.1) (3699.5 4650.94)" "[SmdPin] +1P8VSB_OUT (<uTiL>cId2794<uTiL>.2) (3717.0 4651.0)" list(3717.000000 4651.000000) nil)@@@list("iris_chen" "2017/08/22 17:19:31" nil "P16C000357-PC" "5n-armani13.a00")@@@list("anson_lee" "2017/08/24 14:25:00" nil "P172000029-PC" "5n-armani13.a00.0824") | list("[Spacing] BOTTOM" "183.Shape to Route Keepin" "0 MIL [DEFAULT]" "0 MIL" "0.00 MIL" "DRC ERROR CLASS/BOTTOM" "[Shape] Route Keepin/All ((-191.01 273.9) (8699.38 4792.96))" "[Bottom Shape] GND ((-82.35 273.9) (8493.57 1710.0))" list(3884.420000 504.590000) nil)@@@list("iris_chen" "2017/08/22 17:18:35" nil "P16C000357-PC" "5n-armani13.a00")@@@list("anson_lee" "2017/08/24 14:23:51" nil "P172000029-PC" "5n-armani13.a00.0824") | list("[Physical] BOTTOM" "293.Pad/Pad Direct Connect" "NOT_ALLOWED [(GND_20)]" "ALL_ALLOWED" "" "DRC ERROR CLASS/BOTTOM" "[ThruPin] GND (<uTiL>cId521<uTiL>.15) (4045.0 4696.0)" "[SmdPin] GND (<uTiL>cId521<uTiL>.11) (4066.0 4656.0)" list(4045.000000 4696.000000) nil)@@@list("iris_chen" "2017/08/22 17:19:40" nil "P16C000357-PC" "5n-armani13.a00")@@@list("anson_lee" "2017/08/24 14:25:12" nil "P172000029-PC" "5n-armani13.a00.0824") | list("[Physical] BOTTOM" "359.Pad/Pad Direct Connect" "NOT_ALLOWED [(GND_20)]" "ALL_ALLOWED" "" "DRC ERROR CLASS/BOTTOM" "[SmdPin] GND (<uTiL>cId521<uTiL>.11) (4066.0 4656.0)" "[ThruPin] GND (<uTiL>cId521<uTiL>.14) (4045.0 4616.0)" list(4045.000000 4616.000000) nil)@@@list("iris_chen" "2017/08/22 17:21:17" nil "P16C000357-PC" "5n-armani13.a00")@@@list("anson_lee" "2017/08/24 14:25:58" nil "P172000029-PC" "5n-armani13.a00.0824") | list("[Physical] BOTTOM" "294.Pad/Pad Direct Connect" "NOT_ALLOWED [(GND_20)]" "ALL_ALLOWED" "" "DRC ERROR CLASS/BOTTOM" "[SmdPin] GND (<uTiL>cId521<uTiL>.11) (4066.0 4656.0)" "[ThruPin] GND (<uTiL>cId521<uTiL>.13) (4087.0 4696.0)" list(4087.000000 4696.000000) nil)@@@list("iris_chen" "2017/08/22 17:19:27" nil "P16C000357-PC" "5n-armani13.a00")@@@list("anson_lee" "2017/08/24 14:25:13" nil "P172000029-PC" "5n-armani13.a00.0824") | list("[Physical] BOTTOM" "295.Pad/Pad Direct Connect" "NOT_ALLOWED [(GND_20)]" "ALL_ALLOWED" "" "DRC ERROR CLASS/BOTTOM" "[SmdPin] GND (<uTiL>cId521<uTiL>.11) (4066.0 4656.0)" "[ThruPin] GND (<uTiL>cId521<uTiL>.12) (4087.0 4616.0)" list(4087.000000 4616.000000) nil)@@@list("iris_chen" "2017/08/22 17:19:17" nil "P16C000357-PC" "5n-armani13.a00")@@@list("anson_lee" "2017/08/24 14:25:14" nil "P172000029-PC" "5n-armani13.a00.0824") | list("[Physical] BOTTOM" "298.Pad/Pad Direct Connect" "NOT_ALLOWED [(GND_20)]" "ALL_ALLOWED" "" "DRC ERROR CLASS/BOTTOM" "[SmdPin] GND (<uTiL>cId5906<uTiL>.41) (4225.0 4215.0)" "[ThruPin] GND (<uTiL>cId5906<uTiL>.43) (4168.0 4272.0)" list(4168.000000 4272.000000) nil)@@@list("iris_chen" "2017/08/22 17:19:41" nil "P16C000357-PC" "5n-armani13.a00")@@@list("anson_lee" "2017/08/24 14:25:16" nil "P172000029-PC" "5n-armani13.a00.0824") | list("[Physical] BOTTOM" "296.Pad/Pad Direct Connect" "NOT_ALLOWED [(GND_20)]" "ALL_ALLOWED" "" "DRC ERROR CLASS/BOTTOM" "[ThruPin] GND (<uTiL>cId5906<uTiL>.45) (4168.0 4158.0)" "[SmdPin] GND (<uTiL>cId5906<uTiL>.41) (4225.0 4215.0)" list(4168.000000 4158.000000) nil)@@@list("iris_chen" "2017/08/22 17:21:18" nil "P16C000357-PC" "5n-armani13.a00")@@@list("anson_lee" "2017/08/24 14:25:14" nil "P172000029-PC" "5n-armani13.a00.0824") | list("[Physical] BOTTOM" "360.Pad/Pad Direct Connect" "NOT_ALLOWED [(GND_20)]" "ALL_ALLOWED" "" "DRC ERROR CLASS/BOTTOM" "[SmdPin] GND (<uTiL>cId5906<uTiL>.41) (4225.0 4215.0)" "[ThruPin] GND (<uTiL>cId5906<uTiL>.42) (4282.0 4272.0)" list(4282.000000 4272.000000) nil)@@@list("iris_chen" "2017/08/22 17:19:55" nil "P16C000357-PC" "5n-armani13.a00")@@@list("anson_lee" "2017/08/24 14:25:59" nil "P172000029-PC" "5n-armani13.a00.0824") | list("[Physical] BOTTOM" "297.Pad/Pad Direct Connect" "NOT_ALLOWED [(GND_20)]" "ALL_ALLOWED" "" "DRC ERROR CLASS/BOTTOM" "[SmdPin] GND (<uTiL>cId5906<uTiL>.41) (4225.0 4215.0)" "[ThruPin] GND (<uTiL>cId5906<uTiL>.44) (4282.0 4158.0)" list(4282.000000 4158.000000) nil)@@@list("iris_chen" "2017/08/22 17:19:17" nil "P16C000357-PC" "5n-armani13.a00")@@@list("anson_lee" "2017/08/24 14:25:15" nil "P172000029-PC" "5n-armani13.a00.0824") | list("[Physical] BOTTOM" "324.Pad/Pad Direct Connect" "NOT_ALLOWED [(GND_20)]" "ALL_ALLOWED" "" "DRC ERROR CLASS/BOTTOM" "[SmdPin] GND (<uTiL>cId5764<uTiL>.9) (4674.63 4525.0)" "[ThruPin] GND (<uTiL>cId5764<uTiL>.13) (4634.46 4602.76)" list(4634.460000 4602.760000) nil)@@@list("iris_chen" "2017/08/22 17:19:32" nil "P16C000357-PC" "5n-armani13.a00")@@@list("anson_lee" "2017/08/24 14:25:34" nil "P172000029-PC" "5n-armani13.a00.0824") | list("[Physical] BOTTOM" "287.Pad/Pad Direct Connect" "NOT_ALLOWED [(GND_20)]" "ALL_ALLOWED" "" "DRC ERROR CLASS/BOTTOM" "[SmdPin] GND (<uTiL>cId5764<uTiL>.9) (4674.63 4525.0)" "[ThruPin] GND (<uTiL>cId5764<uTiL>.16) (4634.46 4542.62)" list(4634.460000 4542.620000) nil)@@@list("iris_chen" "2017/08/22 17:19:16" nil "P16C000357-PC" "5n-armani13.a00")@@@list("anson_lee" "2017/08/24 14:25:07" nil "P172000029-PC" "5n-armani13.a00.0824") | list("[Physical] BOTTOM" "285.Pad/Pad Direct Connect" "NOT_ALLOWED [(GND_20)]" "ALL_ALLOWED" "" "DRC ERROR CLASS/BOTTOM" "[ThruPin] GND (<uTiL>cId5764<uTiL>.18) (4634.46 4482.48)" "[SmdPin] GND (<uTiL>cId5764<uTiL>.9) (4674.63 4525.0)" list(4634.460000 4482.480000) nil)@@@list("iris_chen" "2017/08/22 17:19:15" nil "P16C000357-PC" "5n-armani13.a00")@@@list("anson_lee" "2017/08/24 14:25:06" nil "P172000029-PC" "5n-armani13.a00.0824") | list("[Physical] BOTTOM" "286.Pad/Pad Direct Connect" "NOT_ALLOWED [(GND_20)]" "ALL_ALLOWED" "" "DRC ERROR CLASS/BOTTOM" "[SmdPin] GND (<uTiL>cId5764<uTiL>.9) (4674.63 4525.0)" "[ThruPin] GND (<uTiL>cId5764<uTiL>.17) (4669.52 4482.48)" list(4669.520000 4482.480000) nil)@@@list("iris_chen" "2017/08/22 17:19:16" nil "P16C000357-PC" "5n-armani13.a00")@@@list("anson_lee" "2017/08/24 14:25:07" nil "P172000029-PC" "5n-armani13.a00.0824") | list("[Physical] BOTTOM" "325.Pad/Pad Direct Connect" "NOT_ALLOWED [(GND_20)]" "ALL_ALLOWED" "" "DRC ERROR CLASS/BOTTOM" "[SmdPin] GND (<uTiL>cId5764<uTiL>.9) (4674.63 4525.0)" "[ThruPin] GND (<uTiL>cId5764<uTiL>.12) (4674.63 4602.76)" list(4674.630000 4602.760000) nil)@@@list("iris_chen" "2017/08/22 17:19:43" nil "P16C000357-PC" "5n-armani13.a00")@@@list("anson_lee" "2017/08/24 14:25:35" nil "P172000029-PC" "5n-armani13.a00.0824") | list("[Physical] BOTTOM" "288.Pad/Pad Direct Connect" "NOT_ALLOWED [(GND_20)]" "ALL_ALLOWED" "" "DRC ERROR CLASS/BOTTOM" "[SmdPin] GND (<uTiL>cId5764<uTiL>.9) (4674.63 4525.0)" "[ThruPin] GND (<uTiL>cId5764<uTiL>.15) (4674.63 4542.62)" list(4674.630000 4542.620000) nil)@@@list("iris_chen" "2017/08/22 17:21:22" nil "P16C000357-PC" "5n-armani13.a00")@@@list("anson_lee" "2017/08/24 14:25:08" nil "P172000029-PC" "5n-armani13.a00.0824") | list("[Physical] BOTTOM" "371.Pad/Pad Direct Connect" "NOT_ALLOWED [(GND_20)]" "ALL_ALLOWED" "" "DRC ERROR CLASS/BOTTOM" "[SmdPin] GND (<uTiL>cId5764<uTiL>.9) (4674.63 4525.0)" "[ThruPin] GND (<uTiL>cId5764<uTiL>.11) (4714.79 4602.76)" list(4714.790000 4602.760000) nil)@@@list("iris_chen" "2017/08/22 17:21:03" nil "P16C000357-PC" "5n-armani13.a00")@@@list("anson_lee" "2017/08/24 14:26:06" nil "P172000029-PC" "5n-armani13.a00.0824") | list("[Physical] BOTTOM" "323.Pad/Pad Direct Connect" "NOT_ALLOWED [(GND_20)]" "ALL_ALLOWED" "" "DRC ERROR CLASS/BOTTOM" "[SmdPin] GND (<uTiL>cId5764<uTiL>.9) (4674.63 4525.0)" "[ThruPin] GND (<uTiL>cId5764<uTiL>.14) (4714.79 4542.62)" list(4714.790000 4542.620000) nil)@@@list("iris_chen" "2017/08/22 17:19:20" nil "P16C000357-PC" "5n-armani13.a00")@@@list("anson_lee" "2017/08/24 14:25:33" nil "P172000029-PC" "5n-armani13.a00.0824") | list("[Physical] BOTTOM" "279.Pad/Pad Direct Connect" "NOT_ALLOWED [DEFAULT]" "ALL_ALLOWED" "" "DRC ERROR CLASS/BOTTOM" "[SmdPin] N154205542 (<uTiL>cId5927<uTiL>.1) (4845.91 4553.0)" "[SmdPin] N154205542 (<uTiL>cId5632<uTiL>.1) (4892.0 4563.0)" list(4892.000000 4563.000000) nil)@@@list("iris_chen" "2017/08/22 17:21:25" nil "P16C000357-PC" "5n-armani13.a00")@@@list("anson_lee" "2017/08/24 14:25:03" nil "P172000029-PC" "5n-armani13.a00.0824") | list("[Physical] BOTTOM" "327.Pad/Pad Direct Connect" "NOT_ALLOWED [(GND_20)]" "ALL_ALLOWED" "" "DRC ERROR CLASS/BOTTOM" "[SmdPin] GND (<uTiL>cId5765<uTiL>.9) (4979.62 4203.0)" "[ThruPin] GND (<uTiL>cId5765<uTiL>.13) (4939.45 4280.76)" list(4939.450000 4280.760000) nil)@@@list("iris_chen" "2017/08/22 17:21:03" nil "P16C000357-PC" "5n-armani13.a00")@@@list("anson_lee" "2017/08/24 14:25:36" nil "P172000029-PC" "5n-armani13.a00.0824") | list("[Physical] BOTTOM" "326.Pad/Pad Direct Connect" "NOT_ALLOWED [(GND_20)]" "ALL_ALLOWED" "" "DRC ERROR CLASS/BOTTOM" "[SmdPin] GND (<uTiL>cId5765<uTiL>.9) (4979.62 4203.0)" "[ThruPin] GND (<uTiL>cId5765<uTiL>.16) (4939.45 4220.62)" list(4939.450000 4220.620000) nil)@@@list("iris_chen" "2017/08/22 17:19:21" nil "P16C000357-PC" "5n-armani13.a00")@@@list("anson_lee" "2017/08/24 14:25:35" nil "P172000029-PC" "5n-armani13.a00.0824") | list("[Physical] BOTTOM" "284.Pad/Pad Direct Connect" "NOT_ALLOWED [(GND_20)]" "ALL_ALLOWED" "" "DRC ERROR CLASS/BOTTOM" "[ThruPin] GND (<uTiL>cId5765<uTiL>.18) (4939.45 4160.48)" "[SmdPin] GND (<uTiL>cId5765<uTiL>.9) (4979.62 4203.0)" list(4939.450000 4160.480000) nil)@@@list("iris_chen" "2017/08/22 17:21:22" nil "P16C000357-PC" "5n-armani13.a00")@@@list("anson_lee" "2017/08/24 14:25:06" nil "P172000029-PC" "5n-armani13.a00.0824") | list("[Physical] BOTTOM" "370.Pad/Pad Direct Connect" "NOT_ALLOWED [(GND_20)]" "ALL_ALLOWED" "" "DRC ERROR CLASS/BOTTOM" "[SmdPin] GND (<uTiL>cId5765<uTiL>.9) (4979.62 4203.0)" "[ThruPin] GND (<uTiL>cId5765<uTiL>.17) (4974.51 4160.48)" list(4974.510000 4160.480000) nil)@@@list("iris_chen" "2017/08/22 17:19:43" nil "P16C000357-PC" "5n-armani13.a00")@@@list("anson_lee" "2017/08/24 14:26:05" nil "P172000029-PC" "5n-armani13.a00.0824") | list("[Physical] BOTTOM" "330.Pad/Pad Direct Connect" "NOT_ALLOWED [(GND_20)]" "ALL_ALLOWED" "" "DRC ERROR CLASS/BOTTOM" "[SmdPin] GND (<uTiL>cId5765<uTiL>.9) (4979.62 4203.0)" "[ThruPin] GND (<uTiL>cId5765<uTiL>.12) (4979.62 4280.76)" list(4979.620000 4280.760000) nil)@@@list("iris_chen" "2017/08/22 17:19:22" nil "P16C000357-PC" "5n-armani13.a00")@@@list("anson_lee" "2017/08/24 14:25:38" nil "P172000029-PC" "5n-armani13.a00.0824") | list("[Physical] BOTTOM" "328.Pad/Pad Direct Connect" "NOT_ALLOWED [(GND_20)]" "ALL_ALLOWED" "" "DRC ERROR CLASS/BOTTOM" "[SmdPin] GND (<uTiL>cId5765<uTiL>.9) (4979.62 4203.0)" "[ThruPin] GND (<uTiL>cId5765<uTiL>.15) (4979.62 4220.62)" list(4979.620000 4220.620000) nil)@@@list("iris_chen" "2017/08/22 17:19:21" nil "P16C000357-PC" "5n-armani13.a00")@@@list("anson_lee" "2017/08/24 14:25:36" nil "P172000029-PC" "5n-armani13.a00.0824") | list("[Physical] BOTTOM" "369.Pad/Pad Direct Connect" "NOT_ALLOWED [(GND_20)]" "ALL_ALLOWED" "" "DRC ERROR CLASS/BOTTOM" "[SmdPin] GND (<uTiL>cId5765<uTiL>.9) (4979.62 4203.0)" "[ThruPin] GND (<uTiL>cId5765<uTiL>.11) (5019.78 4280.76)" list(5019.780000 4280.760000) nil)@@@list("iris_chen" "2017/08/22 17:19:42" nil "P16C000357-PC" "5n-armani13.a00")@@@list("anson_lee" "2017/08/24 14:26:04" nil "P172000029-PC" "5n-armani13.a00.0824") | list("[Physical] BOTTOM" "329.Pad/Pad Direct Connect" "NOT_ALLOWED [(GND_20)]" "ALL_ALLOWED" "" "DRC ERROR CLASS/BOTTOM" "[SmdPin] GND (<uTiL>cId5765<uTiL>.9) (4979.62 4203.0)" "[ThruPin] GND (<uTiL>cId5765<uTiL>.14) (5019.78 4220.62)" list(5019.780000 4220.620000) nil)@@@list("iris_chen" "2017/08/22 17:19:22" nil "P16C000357-PC" "5n-armani13.a00")@@@list("anson_lee" "2017/08/24 14:25:38" nil "P172000029-PC" "5n-armani13.a00.0824") | list("[Physical] BOTTOM" "365.Pad/Pad Direct Connect" "NOT_ALLOWED [DEFAULT]" "ALL_ALLOWED" "" "DRC ERROR CLASS/BOTTOM" "[SmdPin] +VDDC_VGA (<uTiL>cId5927<uTiL>.2) (5084.09 4553.0)" "[SmdPin] +VDDC_VGA (<uTiL>cId5631<uTiL>.1) (5041.0 4562.0)" list(5041.000000 4562.000000) nil)@@@list("iris_chen" "2017/08/22 17:21:26" nil "P16C000357-PC" "5n-armani13.a00")@@@list("anson_lee" "2017/08/24 14:26:02" nil "P172000029-PC" "5n-armani13.a00.0824") | list("[Physical] BOTTOM" "260.Pad/Pad Direct Connect" "NOT_ALLOWED [DEFAULT]" "ALL_ALLOWED" "" "DRC ERROR CLASS/BOTTOM" "[SmdPin] N154204989 (<uTiL>cId5928<uTiL>.1) (5154.91 4314.0)" "[SmdPin] N154204989 (<uTiL>cId5634<uTiL>.1) (5198.5 4317.0)" list(5198.500000 4317.000000) nil)@@@list("iris_chen" "2017/08/22 17:21:02" nil "P16C000357-PC" "5n-armani13.a00")@@@list("anson_lee" "2017/08/24 14:24:51" nil "P172000029-PC" "5n-armani13.a00.0824") | list("[Physical] BOTTOM" "262.Pad/Pad Direct Connect" "NOT_ALLOWED [DEFAULT]" "ALL_ALLOWED" "" "DRC ERROR CLASS/BOTTOM" "[SmdPin] +VDDC_VGA (<uTiL>cId5928<uTiL>.2) (5393.09 4314.0)" "[SmdPin] +VDDC_VGA (<uTiL>cId5633<uTiL>.1) (5351.5 4314.0)" list(5351.500000 4314.000000) nil)@@@list("iris_chen" "2017/08/22 17:21:25" nil "P16C000357-PC" "5n-armani13.a00")@@@list("anson_lee" "2017/08/24 14:24:53" nil "P172000029-PC" "5n-armani13.a00.0824") | list("[Physical] BOTTOM" "249.Pad/Pad Direct Connect" "NOT_ALLOWED [(PWR_20)]" "ALL_ALLOWED" "" "DRC ERROR CLASS/BOTTOM" "[SmdPin] +VCORE (<uTiL>cId2877<uTiL>.2) (5321.91 2700.0)" "[SmdPin] +VCORE (<uTiL>cId2878<uTiL>.2) (5366.0 2675.0)" list(5366.000000 2675.000000) nil)@@@list("iris_chen" "2017/08/22 17:21:26" nil "P16C000357-PC" "5n-armani13.a00")@@@list("anson_lee" "2017/08/24 14:24:44" nil "P172000029-PC" "5n-armani13.a00.0824") | list("[Physical] BOTTOM" "264.Pad/Pad Direct Connect" "NOT_ALLOWED [(PWR_20)]" "ALL_ALLOWED" "" "DRC ERROR CLASS/BOTTOM" "[SmdPin] +VCCGT (<uTiL>cId1154<uTiL>.2) (5383.0 3020.0)" "[SmdPin] +VCCGT (<uTiL>cId1141<uTiL>.2) (5338.97 3020.0)" list(5383.000000 3020.000000) nil)@@@list("iris_chen" "2017/08/22 17:19:42" nil "P16C000357-PC" "5n-armani13.a00")@@@list("anson_lee" "2017/08/24 14:24:54" nil "P172000029-PC" "5n-armani13.a00.0824") | list("[Physical] BOTTOM" "277.Pad/Pad Direct Connect" "NOT_ALLOWED [(PWR_20)]" "ALL_ALLOWED" "" "DRC ERROR CLASS/BOTTOM" "[SmdPin] +VCORE (<uTiL>cId1158<uTiL>.2) (5391.0 2133.0)" "[SmdPin] +VCORE (<uTiL>cId1142<uTiL>.2) (5346.97 2133.0)" list(5391.000000 2133.000000) nil)@@@list("iris_chen" "2017/08/22 17:21:27" nil "P16C000357-PC" "5n-armani13.a00")@@@list("anson_lee" "2017/08/24 14:25:02" nil "P172000029-PC" "5n-armani13.a00.0824") | list("[Physical] BOTTOM" "347.Pad/Pad Direct Connect" "NOT_ALLOWED [(PWR_20)]" "ALL_ALLOWED" "" "DRC ERROR CLASS/BOTTOM" "[SmdPin] +VCCSA (<uTiL>cId1140<uTiL>.2) (5409.97 1720.0)" "[SmdPin] +VCCSA (<uTiL>cId1156<uTiL>.2) (5454.0 1720.0)" list(5454.000000 1720.000000) nil)@@@list("iris_chen" "2017/08/22 17:21:14" nil "P16C000357-PC" "5n-armani13.a00")@@@list("anson_lee" "2017/08/24 14:25:50" nil "P172000029-PC" "5n-armani13.a00.0824") | list("[Physical] BOTTOM" "281.Pad/Pad Direct Connect" "NOT_ALLOWED [DEFAULT]" "ALL_ALLOWED" "" "DRC ERROR CLASS/BOTTOM" "[SmdPin] PWM2B_SW_OUT_S (<uTiL>cId2877<uTiL>.1) (5560.09 2700.0)" "[SmdPin] PWM2B_SW_OUT_S (<uTiL>cId2879<uTiL>.2) (5517.0 2688.0)" list(5517.000000 2688.000000) nil)@@@list("iris_chen" "2017/08/22 17:21:08" nil "P16C000357-PC" "5n-armani13.a00")@@@list("anson_lee" "2017/08/24 14:25:04" nil "P172000029-PC" "5n-armani13.a00.0824") | list("[Physical] BOTTOM" "396.Pad/Pad Direct Connect" "NOT_ALLOWED [DEFAULT]" "ALL_ALLOWED" "" "DRC ERROR CLASS/BOTTOM" "[SmdPin] PWMA_SW_OUT_S (<uTiL>cId1141<uTiL>.1) (5577.15 3020.0)" "[SmdPin] PWMA_SW_OUT_S (<uTiL>cId1155<uTiL>.2) (5533.0 3020.0)" list(5533.000000 3020.000000) nil)@@@list("iris_chen" "2017/08/22 17:19:31" nil "P16C000357-PC" "5n-armani13.a00")@@@list("anson_lee" "2017/08/24 14:26:22" nil "P172000029-PC" "5n-armani13.a00.0824") | list("[Physical] BOTTOM" "368.Pad/Pad Direct Connect" "NOT_ALLOWED [DEFAULT]" "ALL_ALLOWED" "" "DRC ERROR CLASS/BOTTOM" "[SmdPin] PWM1B_SW_OUT_S (<uTiL>cId1159<uTiL>.2) (5541.0 2133.0)" "[SmdPin] PWM1B_SW_OUT_S (<uTiL>cId1142<uTiL>.1) (5585.15 2133.0)" list(5541.000000 2133.000000) nil)@@@list("iris_chen" "2017/08/22 17:19:14" nil "P16C000357-PC" "5n-armani13.a00")@@@list("anson_lee" "2017/08/24 14:26:04" nil "P172000029-PC" "5n-armani13.a00.0824") | list("[Physical] BOTTOM" "299.Pad/Pad Direct Connect" "NOT_ALLOWED [(GND_20)]" "ALL_ALLOWED" "" "DRC ERROR CLASS/BOTTOM" "[ThruPin] GND (<uTiL>cId529<uTiL>.10) (5547.06 1418.0)" "[SmdPin] GND (<uTiL>cId529<uTiL>.9) (5547.06 1418.0)" list(5547.060000 1418.000000) nil)@@@list("iris_chen" "2017/08/22 17:19:39" nil "P16C000357-PC" "5n-armani13.a00")@@@list("anson_lee" "2017/08/24 14:25:16" nil "P172000029-PC" "5n-armani13.a00.0824") | list("[Physical] BOTTOM" "251.Pad/Pad Direct Connect" "NOT_ALLOWED [(PWR_20)]" "ALL_ALLOWED" "" "DRC ERROR CLASS/BOTTOM" "[SmdPin] +VCCSA_PHASE_D (<uTiL>cId1157<uTiL>.2) (5604.0 1715.0)" "[SmdPin] +VCCSA_PHASE_D (<uTiL>cId1140<uTiL>.1) (5648.15 1720.0)" list(5604.000000 1715.000000) nil)@@@list("iris_chen" "2017/08/22 17:21:02" nil "P16C000357-PC" "5n-armani13.a00")@@@list("anson_lee" "2017/08/24 14:24:46" nil "P172000029-PC" "5n-armani13.a00.0824") | list("[Physical] BOTTOM" "308.Pad/Pad Direct Connect" "NOT_ALLOWED [(GND_20)]" "ALL_ALLOWED" "" "DRC ERROR CLASS/BOTTOM" "[SmdPin] GND (<uTiL>cId2874<uTiL>.9) (5729.27 2696.0)" "[ThruPin] GND (<uTiL>cId2874<uTiL>.14) (5689.11 2678.38)" list(5689.110000 2678.380000) nil)@@@list("iris_chen" "2017/08/22 17:21:07" nil "P16C000357-PC" "5n-armani13.a00")@@@list("anson_lee" "2017/08/24 14:25:22" nil "P172000029-PC" "5n-armani13.a00.0824") | list("[Physical] BOTTOM" "311.Pad/Pad Direct Connect" "NOT_ALLOWED [(GND_20)]" "ALL_ALLOWED" "" "DRC ERROR CLASS/BOTTOM" "[SmdPin] GND (<uTiL>cId2874<uTiL>.9) (5729.27 2696.0)" "[ThruPin] GND (<uTiL>cId2874<uTiL>.11) (5689.11 2618.24)" list(5689.110000 2618.240000) nil)@@@list("iris_chen" "2017/08/22 17:21:04" nil "P16C000357-PC" "5n-armani13.a00")@@@list("anson_lee" "2017/08/24 14:25:23" nil "P172000029-PC" "5n-armani13.a00.0824") | list("[Physical] BOTTOM" "373.Pad/Pad Direct Connect" "NOT_ALLOWED [(GND_20)]" "ALL_ALLOWED" "" "DRC ERROR CLASS/BOTTOM" "[ThruPin] GND (<uTiL>cId1118<uTiL>.14) (5703.11 3053.38)" "[SmdPin] GND (<uTiL>cId1118<uTiL>.9) (5743.27 3071.0)" list(5703.110000 3053.380000) nil)@@@list("iris_chen" "2017/08/22 17:19:33" nil "P16C000357-PC" "5n-armani13.a00")@@@list("anson_lee" "2017/08/24 14:26:07" nil "P172000029-PC" "5n-armani13.a00.0824") | list("[Physical] BOTTOM" "376.Pad/Pad Direct Connect" "NOT_ALLOWED [(GND_20)]" "ALL_ALLOWED" "" "DRC ERROR CLASS/BOTTOM" "[ThruPin] GND (<uTiL>cId1118<uTiL>.11) (5703.11 2993.24)" "[SmdPin] GND (<uTiL>cId1118<uTiL>.9) (5743.27 3071.0)" list(5703.110000 2993.240000) nil)@@@list("iris_chen" "2017/08/22 17:19:34" nil "P16C000357-PC" "5n-armani13.a00")@@@list("anson_lee" "2017/08/24 14:26:09" nil "P172000029-PC" "5n-armani13.a00.0824") | list("[Physical] BOTTOM" "301.Pad/Pad Direct Connect" "NOT_ALLOWED [(GND_20)]" "ALL_ALLOWED" "" "DRC ERROR CLASS/BOTTOM" "[SmdPin] GND (<uTiL>cId1119<uTiL>.9) (5760.27 2140.0)" "[ThruPin] GND (<uTiL>cId1119<uTiL>.14) (5720.11 2122.38)" list(5720.110000 2122.380000) nil)@@@list("iris_chen" "2017/08/22 17:19:18" nil "P16C000357-PC" "5n-armani13.a00")@@@list("anson_lee" "2017/08/24 14:25:17" nil "P172000029-PC" "5n-armani13.a00.0824") | list("[Physical] BOTTOM" "304.Pad/Pad Direct Connect" "NOT_ALLOWED [(GND_20)]" "ALL_ALLOWED" "" "DRC ERROR CLASS/BOTTOM" "[SmdPin] GND (<uTiL>cId1119<uTiL>.9) (5760.27 2140.0)" "[ThruPin] GND (<uTiL>cId1119<uTiL>.11) (5720.11 2062.24)" list(5720.110000 2062.240000) nil)@@@list("iris_chen" "2017/08/22 17:19:19" nil "P16C000357-PC" "5n-armani13.a00")@@@list("anson_lee" "2017/08/24 14:25:19" nil "P172000029-PC" "5n-armani13.a00.0824") | list("[Physical] BOTTOM" "307.Pad/Pad Direct Connect" "NOT_ALLOWED [(GND_20)]" "ALL_ALLOWED" "" "DRC ERROR CLASS/BOTTOM" "[SmdPin] GND (<uTiL>cId2874<uTiL>.9) (5729.27 2696.0)" "[ThruPin] GND (<uTiL>cId2874<uTiL>.15) (5729.27 2678.38)" list(5729.270000 2678.380000) nil)@@@list("iris_chen" "2017/08/22 17:21:06" nil "P16C000357-PC" "5n-armani13.a00")@@@list("anson_lee" "2017/08/24 14:25:21" nil "P172000029-PC" "5n-armani13.a00.0824") | list("[Physical] BOTTOM" "310.Pad/Pad Direct Connect" "NOT_ALLOWED [(GND_20)]" "ALL_ALLOWED" "" "DRC ERROR CLASS/BOTTOM" "[SmdPin] GND (<uTiL>cId2874<uTiL>.9) (5729.27 2696.0)" "[ThruPin] GND (<uTiL>cId2874<uTiL>.12) (5729.27 2618.24)" list(5729.270000 2618.240000) nil)@@@list("iris_chen" "2017/08/22 17:21:05" nil "P16C000357-PC" "5n-armani13.a00")@@@list("anson_lee" "2017/08/24 14:25:23" nil "P172000029-PC" "5n-armani13.a00.0824") | list("[Physical] BOTTOM" "306.Pad/Pad Direct Connect" "NOT_ALLOWED [(GND_20)]" "ALL_ALLOWED" "" "DRC ERROR CLASS/BOTTOM" "[SmdPin] GND (<uTiL>cId2874<uTiL>.9) (5729.27 2696.0)" "[ThruPin] GND (<uTiL>cId2874<uTiL>.17) (5734.38 2738.52)" list(5734.380000 2738.520000) nil)@@@list("iris_chen" "2017/08/22 17:21:23" nil "P16C000357-PC" "5n-armani13.a00")@@@list("anson_lee" "2017/08/24 14:25:20" nil "P172000029-PC" "5n-armani13.a00.0824") | list("[Physical] BOTTOM" "379.Pad/Pad Direct Connect" "NOT_ALLOWED [(GND_20)]" "ALL_ALLOWED" "" "DRC ERROR CLASS/BOTTOM" "[SmdPin] GND (<uTiL>cId1118<uTiL>.9) (5743.27 3071.0)" "[ThruPin] GND (<uTiL>cId1118<uTiL>.15) (5743.27 3053.38)" list(5743.270000 3053.380000) nil)@@@list("iris_chen" "2017/08/22 17:19:35" nil "P16C000357-PC" "5n-armani13.a00")@@@list("anson_lee" "2017/08/24 14:26:11" nil "P172000029-PC" "5n-armani13.a00.0824") | list("[Physical] BOTTOM" "377.Pad/Pad Direct Connect" "NOT_ALLOWED [(GND_20)]" "ALL_ALLOWED" "" "DRC ERROR CLASS/BOTTOM" "[ThruPin] GND (<uTiL>cId1118<uTiL>.12) (5743.27 2993.24)" "[SmdPin] GND (<uTiL>cId1118<uTiL>.9) (5743.27 3071.0)" list(5743.270000 2993.240000) nil)@@@list("iris_chen" "2017/08/22 17:19:34" nil "P16C000357-PC" "5n-armani13.a00")@@@list("anson_lee" "2017/08/24 14:26:10" nil "P172000029-PC" "5n-armani13.a00.0824") | list("[Physical] BOTTOM" "375.Pad/Pad Direct Connect" "NOT_ALLOWED [(GND_20)]" "ALL_ALLOWED" "" "DRC ERROR CLASS/BOTTOM" "[ThruPin] GND (<uTiL>cId1118<uTiL>.17) (5748.38 3113.52)" "[SmdPin] GND (<uTiL>cId1118<uTiL>.9) (5743.27 3071.0)" list(5748.380000 3113.520000) nil)@@@list("iris_chen" "2017/08/22 17:19:33" nil "P16C000357-PC" "5n-armani13.a00")@@@list("anson_lee" "2017/08/24 14:26:08" nil "P172000029-PC" "5n-armani13.a00.0824") | list("[Physical] BOTTOM" "372.Pad/Pad Direct Connect" "NOT_ALLOWED [(GND_20)]" "ALL_ALLOWED" "" "DRC ERROR CLASS/BOTTOM" "[SmdPin] GND (<uTiL>cId1119<uTiL>.9) (5760.27 2140.0)" "[ThruPin] GND (<uTiL>cId1119<uTiL>.15) (5760.27 2122.38)" list(5760.270000 2122.380000) nil)@@@list("iris_chen" "2017/08/22 17:21:23" nil "P16C000357-PC" "5n-armani13.a00")@@@list("anson_lee" "2017/08/24 14:26:07" nil "P172000029-PC" "5n-armani13.a00.0824") | list("[Physical] BOTTOM" "303.Pad/Pad Direct Connect" "NOT_ALLOWED [(GND_20)]" "ALL_ALLOWED" "" "DRC ERROR CLASS/BOTTOM" "[SmdPin] GND (<uTiL>cId1119<uTiL>.9) (5760.27 2140.0)" "[ThruPin] GND (<uTiL>cId1119<uTiL>.12) (5760.27 2062.24)" list(5760.270000 2062.240000) nil)@@@list("iris_chen" "2017/08/22 17:19:18" nil "P16C000357-PC" "5n-armani13.a00")@@@list("anson_lee" "2017/08/24 14:25:18" nil "P172000029-PC" "5n-armani13.a00.0824") | list("[Physical] BOTTOM" "322.Pad/Pad Direct Connect" "NOT_ALLOWED [(GND_20)]" "ALL_ALLOWED" "" "DRC ERROR CLASS/BOTTOM" "[SmdPin] GND (<uTiL>cId1119<uTiL>.9) (5760.27 2140.0)" "[ThruPin] GND (<uTiL>cId1119<uTiL>.17) (5765.38 2182.52)" list(5765.380000 2182.520000) nil)@@@list("iris_chen" "2017/08/22 17:19:20" nil "P16C000357-PC" "5n-armani13.a00")@@@list("anson_lee" "2017/08/24 14:25:32" nil "P172000029-PC" "5n-armani13.a00.0824") | list("[Physical] BOTTOM" "305.Pad/Pad Direct Connect" "NOT_ALLOWED [(GND_20)]" "ALL_ALLOWED" "" "DRC ERROR CLASS/BOTTOM" "[ThruPin] GND (<uTiL>cId2874<uTiL>.18) (5769.44 2738.52)" "[SmdPin] GND (<uTiL>cId2874<uTiL>.9) (5729.27 2696.0)" list(5769.440000 2738.520000) nil)@@@list("iris_chen" "2017/08/22 17:21:07" nil "P16C000357-PC" "5n-armani13.a00")@@@list("anson_lee" "2017/08/24 14:25:20" nil "P172000029-PC" "5n-armani13.a00.0824") | list("[Physical] BOTTOM" "381.Pad/Pad Direct Connect" "NOT_ALLOWED [(GND_20)]" "ALL_ALLOWED" "" "DRC ERROR CLASS/BOTTOM" "[SmdPin] GND (<uTiL>cId2874<uTiL>.9) (5729.27 2696.0)" "[ThruPin] GND (<uTiL>cId2874<uTiL>.16) (5769.44 2678.38)" list(5769.440000 2678.380000) nil)@@@list("iris_chen" "2017/08/22 17:21:06" nil "P16C000357-PC" "5n-armani13.a00")@@@list("anson_lee" "2017/08/24 14:26:12" nil "P172000029-PC" "5n-armani13.a00.0824") | list("[Physical] BOTTOM" "309.Pad/Pad Direct Connect" "NOT_ALLOWED [(GND_20)]" "ALL_ALLOWED" "" "DRC ERROR CLASS/BOTTOM" "[SmdPin] GND (<uTiL>cId2874<uTiL>.9) (5729.27 2696.0)" "[ThruPin] GND (<uTiL>cId2874<uTiL>.13) (5769.44 2618.24)" list(5769.440000 2618.240000) nil)@@@list("iris_chen" "2017/08/22 17:21:05" nil "P16C000357-PC" "5n-armani13.a00")@@@list("anson_lee" "2017/08/24 14:25:22" nil "P172000029-PC" "5n-armani13.a00.0824") | list("[Physical] BOTTOM" "380.Pad/Pad Direct Connect" "NOT_ALLOWED [(GND_20)]" "ALL_ALLOWED" "" "DRC ERROR CLASS/BOTTOM" "[SmdPin] GND (<uTiL>cId1118<uTiL>.9) (5743.27 3071.0)" "[ThruPin] GND (<uTiL>cId1118<uTiL>.18) (5783.44 3113.52)" list(5783.440000 3113.520000) nil)@@@list("iris_chen" "2017/08/22 17:19:35" nil "P16C000357-PC" "5n-armani13.a00")@@@list("anson_lee" "2017/08/24 14:26:11" nil "P172000029-PC" "5n-armani13.a00.0824") | list("[Physical] BOTTOM" "374.Pad/Pad Direct Connect" "NOT_ALLOWED [(GND_20)]" "ALL_ALLOWED" "" "DRC ERROR CLASS/BOTTOM" "[ThruPin] GND (<uTiL>cId1118<uTiL>.16) (5783.44 3053.38)" "[SmdPin] GND (<uTiL>cId1118<uTiL>.9) (5743.27 3071.0)" list(5783.440000 3053.380000) nil)@@@list("iris_chen" "2017/08/22 17:21:04" nil "P16C000357-PC" "5n-armani13.a00")@@@list("anson_lee" "2017/08/24 14:26:08" nil "P172000029-PC" "5n-armani13.a00.0824") | list("[Physical] BOTTOM" "378.Pad/Pad Direct Connect" "NOT_ALLOWED [(GND_20)]" "ALL_ALLOWED" "" "DRC ERROR CLASS/BOTTOM" "[ThruPin] GND (<uTiL>cId1118<uTiL>.13) (5783.44 2993.24)" "[SmdPin] GND (<uTiL>cId1118<uTiL>.9) (5743.27 3071.0)" list(5783.440000 2993.240000) nil)@@@list("iris_chen" "2017/08/22 17:19:44" nil "P16C000357-PC" "5n-armani13.a00")@@@list("anson_lee" "2017/08/24 14:26:10" nil "P172000029-PC" "5n-armani13.a00.0824") | list("[Physical] BOTTOM" "321.Pad/Pad Direct Connect" "NOT_ALLOWED [(GND_20)]" "ALL_ALLOWED" "" "DRC ERROR CLASS/BOTTOM" "[SmdPin] GND (<uTiL>cId1119<uTiL>.9) (5760.27 2140.0)" "[ThruPin] GND (<uTiL>cId1119<uTiL>.18) (5800.44 2182.52)" list(5800.440000 2182.520000) nil)@@@list("iris_chen" "2017/08/22 17:19:19" nil "P16C000357-PC" "5n-armani13.a00")@@@list("anson_lee" "2017/08/24 14:25:32" nil "P172000029-PC" "5n-armani13.a00.0824") | list("[Physical] BOTTOM" "300.Pad/Pad Direct Connect" "NOT_ALLOWED [(GND_20)]" "ALL_ALLOWED" "" "DRC ERROR CLASS/BOTTOM" "[ThruPin] GND (<uTiL>cId1119<uTiL>.16) (5800.44 2122.38)" "[SmdPin] GND (<uTiL>cId1119<uTiL>.9) (5760.27 2140.0)" list(5800.440000 2122.380000) nil)@@@list("iris_chen" "2017/08/22 17:19:32" nil "P16C000357-PC" "5n-armani13.a00")@@@list("anson_lee" "2017/08/24 14:25:17" nil "P172000029-PC" "5n-armani13.a00.0824") | list("[Physical] BOTTOM" "302.Pad/Pad Direct Connect" "NOT_ALLOWED [(GND_20)]" "ALL_ALLOWED" "" "DRC ERROR CLASS/BOTTOM" "[SmdPin] GND (<uTiL>cId1119<uTiL>.9) (5760.27 2140.0)" "[ThruPin] GND (<uTiL>cId1119<uTiL>.13) (5800.44 2062.24)" list(5800.440000 2062.240000) nil)@@@list("iris_chen" "2017/08/22 17:19:44" nil "P16C000357-PC" "5n-armani13.a00")@@@list("anson_lee" "2017/08/24 14:25:18" nil "P172000029-PC" "5n-armani13.a00.0824") | list("[Physical] BOTTOM" "271.Pad/Pad Direct Connect" "NOT_ALLOWED [(PWR_20)]" "ALL_ALLOWED" "" "DRC ERROR CLASS/BOTTOM" "[SmdPin] +AC_BAT_SYS (<uTiL>cId6638<uTiL>.2) (5831.1 1330.5)" "[SmdPin] +AC_BAT_SYS (<uTiL>cId1022<uTiL>.1) (5832.0 1346.37)" list(5831.100000 1330.500000) nil)@@@list("iris_chen" "2017/08/22 17:19:40" nil "P16C000357-PC" "5n-armani13.a00")@@@list("anson_lee" "2017/08/24 14:24:58" nil "P172000029-PC" "5n-armani13.a00.0824") | list("[Physical] BOTTOM" "263.Pad/Pad Direct Connect" "NOT_ALLOWED [DEFAULT]" "ALL_ALLOWED" "" "DRC ERROR CLASS/BOTTOM" "[SmdPin] CSON_R (<uTiL>cId1022<uTiL>.2) (5832.0 1267.63)" "[SmdPin] CSON_R (<uTiL>cId6637<uTiL>.2) (5831.1 1282.5)" list(5831.100000 1282.500000) nil)@@@list("iris_chen" "2017/08/22 17:19:53" nil "P16C000357-PC" "5n-armani13.a00")@@@list("anson_lee" "2017/08/24 14:24:53" nil "P172000029-PC" "5n-armani13.a00.0824") | list("[Spacing] BOTTOM" "176.Shape to Route Keepin" "0 MIL [DEFAULT]" "0 MIL" "0.00 MIL" "DRC ERROR CLASS/BOTTOM" "[Shape] Route Keepin/All ((-191.01 273.9) (8699.38 4792.96))" "[Bottom Shape] GND ((5916.11 599.2) (6172.25 634.45))" list(5916.110000 607.210000) nil)@@@list("iris_chen" "2017/08/22 17:18:40" nil "P16C000357-PC" "5n-armani13.a00")@@@list("anson_lee" "2017/08/24 14:23:19" nil "P172000029-PC" "5n-armani13.a00.0824") | list("[Spacing] BOTTOM" "175.Shape to Route Keepout" "0 MIL [DEFAULT]" "0 MIL" "0.00 MIL" "DRC ERROR CLASS/BOTTOM" "[Shape] Route Keepout/All ((-211.01 253.9) (8719.38 4812.96))" "[Bottom Shape] GND ((5916.11 599.2) (6172.25 634.45))" list(5916.110000 599.210000) nil)@@@list("iris_chen" "2017/08/22 17:18:40" nil "P16C000357-PC" "5n-armani13.a00")@@@list("anson_lee" "2017/08/24 14:23:18" nil "P172000029-PC" "5n-armani13.a00.0824") | list("[Physical] BOTTOM" "391.Pad/Pad Direct Connect" "NOT_ALLOWED [(PWR_20)]" "ALL_ALLOWED" "" "DRC ERROR CLASS/BOTTOM" "[SmdPin] +CPU_VIN (<uTiL>cId809<uTiL>.1) (6058.06 1579.37)" "[SmdPin] +CPU_VIN (<uTiL>cId1160<uTiL>.2) (6048.0 1561.0)" list(6048.000000 1561.000000) nil)@@@list("iris_chen" "2017/08/22 17:21:21" nil "P16C000357-PC" "5n-armani13.a00")@@@nil | list("[Physical] BOTTOM" "354.Pad/Pad Direct Connect" "NOT_ALLOWED [(GND_20)]" "ALL_ALLOWED" "" "DRC ERROR CLASS/BOTTOM" "[SmdPin] GND (<uTiL>cId2826<uTiL>.9) (6094.06 2395.0)" "[ThruPin] GND (<uTiL>cId2826<uTiL>.10) (6094.06 2395.0)" list(6094.060000 2395.000000) nil)@@@list("iris_chen" "2017/08/22 17:21:13" nil "P16C000357-PC" "5n-armani13.a00")@@@list("anson_lee" "2017/08/24 14:25:55" nil "P172000029-PC" "5n-armani13.a00.0824") | list("[Physical] BOTTOM" "353.Pad/Pad Direct Connect" "NOT_ALLOWED [(GND_20)]" "ALL_ALLOWED" "" "DRC ERROR CLASS/BOTTOM" "[ThruPin] GND (<uTiL>cId528<uTiL>.10) (6096.06 2030.0)" "[SmdPin] GND (<uTiL>cId528<uTiL>.9) (6096.06 2030.0)" list(6096.060000 2030.000000) nil)@@@list("iris_chen" "2017/08/22 17:19:17" nil "P16C000357-PC" "5n-armani13.a00")@@@list("anson_lee" "2017/08/24 14:25:54" nil "P172000029-PC" "5n-armani13.a00.0824") | list("[Physical] BOTTOM" "312.Pad/Pad Direct Connect" "NOT_ALLOWED [(GND_20)]" "ALL_ALLOWED" "" "DRC ERROR CLASS/BOTTOM" "[ThruPin] GND (<uTiL>cId527<uTiL>.10) (6124.06 2800.0)" "[SmdPin] GND (<uTiL>cId527<uTiL>.9) (6124.06 2800.0)" list(6124.060000 2800.000000) nil)@@@list("iris_chen" "2017/08/22 17:21:13" nil "P16C000357-PC" "5n-armani13.a00")@@@list("anson_lee" "2017/08/24 14:25:25" nil "P172000029-PC" "5n-armani13.a00.0824") | list("[Physical] BOTTOM" "395.Pad/Pad Direct Connect" "NOT_ALLOWED [DEFAULT]" "ALL_ALLOWED" "" "DRC ERROR CLASS/BOTTOM" "[SmdPin] +1.8VO_VGA (<uTiL>cId5938<uTiL>.1) (6142.0 3066.06)" "[SmdPin] +1.8VO_VGA (<uTiL>cId5636<uTiL>.1) (6144.0 3076.0)" list(6144.000000 3076.000000) nil)@@@list("iris_chen" "2017/08/22 17:21:08" nil "P16C000357-PC" "5n-armani13.a00")@@@list("anson_lee" "2017/08/24 14:26:22" nil "P172000029-PC" "5n-armani13.a00.0824") | list("[Physical] BOTTOM" "256.Pad/Pad Direct Connect" "NOT_ALLOWED [(PWR_20)]" "ALL_ALLOWED" "" "DRC ERROR CLASS/BOTTOM" "[SmdPin] +AC_BAT_SYS (<uTiL>cId1160<uTiL>.2) (6194.0 1523.0)" "[SmdPin] +AC_BAT_SYS (<uTiL>cId1317<uTiL>.1) (6195.0 1511.3)" list(6194.000000 1523.000000) nil)@@@list("iris_chen" "2017/08/23 17:49:27" nil "P16C000357-PC" "5n-armani13.a00")@@@list("anson_lee" "2017/08/24 14:24:49" nil "P172000029-PC" "5n-armani13.a00.0824") | list("[Physical] BOTTOM" "313.Pad/Pad Direct Connect" "NOT_ALLOWED [(GND_20)]" "ALL_ALLOWED" "" "DRC ERROR CLASS/BOTTOM" "[ThruPin] GND (<uTiL>cId5905<uTiL>.10) (6228.5 2875.0)" "[SmdPin] GND (<uTiL>cId5905<uTiL>.9) (6250.0 2880.0)" list(6228.500000 2875.000000) nil)@@@list("iris_chen" "2017/08/22 17:21:18" nil "P16C000357-PC" "5n-armani13.a00")@@@list("anson_lee" "2017/08/24 14:25:26" nil "P172000029-PC" "5n-armani13.a00.0824") | list("[Physical] BOTTOM" "267.Pad/Pad Direct Connect" "NOT_ALLOWED [(PWR_20)]" "ALL_ALLOWED" "" "DRC ERROR CLASS/BOTTOM" "[SmdPin] +1.0VO (<uTiL>cId5996<uTiL>.1) (6266.94 2166.0)" "[SmdPin] +1.0VO (<uTiL>cId5989<uTiL>.2) (6258.0 2166.0)" list(6258.000000 2166.000000) nil)@@@list("iris_chen" "2017/08/22 17:21:01" nil "P16C000357-PC" "5n-armani13.a00")@@@list("anson_lee" "2017/08/24 14:24:56" nil "P172000029-PC" "5n-armani13.a00.0824") | list("[Physical] BOTTOM" "366.Pad/Pad Direct Connect" "NOT_ALLOWED [DEFAULT]" "ALL_ALLOWED" "" "DRC ERROR CLASS/BOTTOM" "[SmdPin] +0P95VO (<uTiL>cId5936<uTiL>.1) (6393.0 4590.06)" "[SmdPin] +0P95VO (<uTiL>cId5635<uTiL>.1) (6393.0 4596.0)" list(6393.000000 4596.000000) nil)@@@list("iris_chen" "2017/08/22 17:21:14" nil "P16C000357-PC" "5n-armani13.a00")@@@list("anson_lee" "2017/08/24 14:26:03" nil "P172000029-PC" "5n-armani13.a00.0824") | list("[Physical] BOTTOM" "356.Pad/Pad Direct Connect" "NOT_ALLOWED [(GND_20)]" "ALL_ALLOWED" "" "DRC ERROR CLASS/BOTTOM" "[ThruPin] GND (<uTiL>cId5818<uTiL>.13) (6460.0 4676.0)" "[SmdPin] GND (<uTiL>cId5818<uTiL>.11) (6500.0 4655.0)" list(6460.000000 4676.000000) nil)@@@list("iris_chen" "2017/08/22 17:19:53" nil "P16C000357-PC" "5n-armani13.a00")@@@list("anson_lee" "2017/08/24 14:25:56" nil "P172000029-PC" "5n-armani13.a00.0824") | list("[Physical] BOTTOM" "357.Pad/Pad Direct Connect" "NOT_ALLOWED [(GND_20)]" "ALL_ALLOWED" "" "DRC ERROR CLASS/BOTTOM" "[ThruPin] GND (<uTiL>cId5818<uTiL>.15) (6460.0 4634.0)" "[SmdPin] GND (<uTiL>cId5818<uTiL>.11) (6500.0 4655.0)" list(6460.000000 4634.000000) nil)@@@list("iris_chen" "2017/08/22 17:19:54" nil "P16C000357-PC" "5n-armani13.a00")@@@list("anson_lee" "2017/08/24 14:25:57" nil "P172000029-PC" "5n-armani13.a00.0824") | list("[Physical] BOTTOM" "355.Pad/Pad Direct Connect" "NOT_ALLOWED [(GND_20)]" "ALL_ALLOWED" "" "DRC ERROR CLASS/BOTTOM" "[ThruPin] GND (<uTiL>cId5818<uTiL>.12) (6540.0 4676.0)" "[SmdPin] GND (<uTiL>cId5818<uTiL>.11) (6500.0 4655.0)" list(6540.000000 4676.000000) nil)@@@list("iris_chen" "2017/08/22 17:19:55" nil "P16C000357-PC" "5n-armani13.a00")@@@list("anson_lee" "2017/08/24 14:25:56" nil "P172000029-PC" "5n-armani13.a00.0824") | list("[Physical] BOTTOM" "358.Pad/Pad Direct Connect" "NOT_ALLOWED [(GND_20)]" "ALL_ALLOWED" "" "DRC ERROR CLASS/BOTTOM" "[SmdPin] GND (<uTiL>cId5818<uTiL>.11) (6500.0 4655.0)" "[ThruPin] GND (<uTiL>cId5818<uTiL>.14) (6540.0 4634.0)" list(6540.000000 4634.000000) nil)@@@list("iris_chen" "2017/08/22 17:19:54" nil "P16C000357-PC" "5n-armani13.a00")@@@list("anson_lee" "2017/08/24 14:25:57" nil "P172000029-PC" "5n-armani13.a00.0824") | list("[Physical] BOTTOM" "364.Pad/Pad Direct Connect" "NOT_ALLOWED [(GND_20)]" "ALL_ALLOWED" "" "DRC ERROR CLASS/BOTTOM" "[SmdPin] GND (<uTiL>cId531<uTiL>.41) (6675.0 2185.0)" "[ThruPin] GND (<uTiL>cId531<uTiL>.46) (6618.0 2242.0)" list(6618.000000 2242.000000) nil)@@@list("iris_chen" "2017/08/22 17:19:41" nil "P16C000357-PC" "5n-armani13.a00")@@@list("anson_lee" "2017/08/24 14:26:01" nil "P172000029-PC" "5n-armani13.a00.0824") | list("[Physical] BOTTOM" "315.Pad/Pad Direct Connect" "NOT_ALLOWED [(GND_20)]" "ALL_ALLOWED" "" "DRC ERROR CLASS/BOTTOM" "[SmdPin] GND (<uTiL>cId531<uTiL>.41) (6675.0 2185.0)" "[ThruPin] GND (<uTiL>cId531<uTiL>.42) (6618.0 2128.0)" list(6618.000000 2128.000000) nil)@@@list("iris_chen" "2017/08/22 17:19:30" nil "P16C000357-PC" "5n-armani13.a00")@@@list("anson_lee" "2017/08/24 14:25:28" nil "P172000029-PC" "5n-armani13.a00.0824") | list("[Physical] BOTTOM" "318.Pad/Pad Direct Connect" "NOT_ALLOWED [(GND_20)]" "ALL_ALLOWED" "" "DRC ERROR CLASS/BOTTOM" "[SmdPin] GND (<uTiL>cId531<uTiL>.41) (6675.0 2185.0)" "[ThruPin] GND (<uTiL>cId531<uTiL>.47) (6638.0 2242.0)" list(6638.000000 2242.000000) nil)@@@list("iris_chen" "2017/08/22 17:19:29" nil "P16C000357-PC" "5n-armani13.a00")@@@list("anson_lee" "2017/08/24 14:25:30" nil "P172000029-PC" "5n-armani13.a00.0824") | list("[Physical] BOTTOM" "314.Pad/Pad Direct Connect" "NOT_ALLOWED [(GND_20)]" "ALL_ALLOWED" "" "DRC ERROR CLASS/BOTTOM" "[ThruPin] GND (<uTiL>cId531<uTiL>.43) (6638.0 2128.0)" "[SmdPin] GND (<uTiL>cId531<uTiL>.41) (6675.0 2185.0)" list(6638.000000 2128.000000) nil)@@@list("iris_chen" "2017/08/22 17:19:30" nil "P16C000357-PC" "5n-armani13.a00")@@@list("anson_lee" "2017/08/24 14:25:27" nil "P172000029-PC" "5n-armani13.a00.0824") | list("[Physical] BOTTOM" "320.Pad/Pad Direct Connect" "NOT_ALLOWED [(GND_20)]" "ALL_ALLOWED" "" "DRC ERROR CLASS/BOTTOM" "[SmdPin] GND (<uTiL>cId531<uTiL>.41) (6675.0 2185.0)" "[ThruPin] GND (<uTiL>cId531<uTiL>.48) (6712.0 2242.0)" list(6712.000000 2242.000000) nil)@@@list("iris_chen" "2017/08/22 17:19:28" nil "P16C000357-PC" "5n-armani13.a00")@@@list("anson_lee" "2017/08/24 14:25:31" nil "P172000029-PC" "5n-armani13.a00.0824") | list("[Physical] BOTTOM" "317.Pad/Pad Direct Connect" "NOT_ALLOWED [(GND_20)]" "ALL_ALLOWED" "" "DRC ERROR CLASS/BOTTOM" "[SmdPin] GND (<uTiL>cId531<uTiL>.41) (6675.0 2185.0)" "[ThruPin] GND (<uTiL>cId531<uTiL>.44) (6712.0 2128.0)" list(6712.000000 2128.000000) nil)@@@list("iris_chen" "2017/08/22 17:19:29" nil "P16C000357-PC" "5n-armani13.a00")@@@list("anson_lee" "2017/08/24 14:25:29" nil "P172000029-PC" "5n-armani13.a00.0824") | list("[Physical] BOTTOM" "319.Pad/Pad Direct Connect" "NOT_ALLOWED [(GND_20)]" "ALL_ALLOWED" "" "DRC ERROR CLASS/BOTTOM" "[SmdPin] GND (<uTiL>cId531<uTiL>.41) (6675.0 2185.0)" "[ThruPin] GND (<uTiL>cId531<uTiL>.49) (6732.0 2242.0)" list(6732.000000 2242.000000) nil)@@@list("iris_chen" "2017/08/22 17:19:57" nil "P16C000357-PC" "5n-armani13.a00")@@@list("anson_lee" "2017/08/24 14:25:30" nil "P172000029-PC" "5n-armani13.a00.0824") | list("[Physical] BOTTOM" "316.Pad/Pad Direct Connect" "NOT_ALLOWED [(GND_20)]" "ALL_ALLOWED" "" "DRC ERROR CLASS/BOTTOM" "[SmdPin] GND (<uTiL>cId531<uTiL>.41) (6675.0 2185.0)" "[ThruPin] GND (<uTiL>cId531<uTiL>.45) (6732.0 2128.0)" list(6732.000000 2128.000000) nil)@@@list("iris_chen" "2017/08/22 17:21:20" nil "P16C000357-PC" "5n-armani13.a00")@@@list("anson_lee" "2017/08/24 14:25:28" nil "P172000029-PC" "5n-armani13.a00.0824") | list("[Physical] BOTTOM" "266.Pad/Pad Direct Connect" "NOT_ALLOWED [DEFAULT]" "ALL_ALLOWED" "" "DRC ERROR CLASS/BOTTOM" "[SmdPin] N152966728 (<uTiL>cId5746<uTiL>.1) (6755.0 2900.94)" "[SmdPin] N152966728 (<uTiL>cId5630<uTiL>.1) (6738.0 2900.0)" list(6738.000000 2900.000000) nil)@@@list("iris_chen" "2017/08/22 17:21:21" nil "P16C000357-PC" "5n-armani13.a00")@@@list("anson_lee" "2017/08/24 14:24:55" nil "P172000029-PC" "5n-armani13.a00.0824") | list("[Physical] BOTTOM" "276.Pad/Pad Direct Connect" "NOT_ALLOWED [(PWR_25)]" "ALL_ALLOWED" "" "DRC ERROR CLASS/BOTTOM" "[SmdPin] N144773400 (<uTiL>cId1167<uTiL>.1) (6972.86 2647.6)" "[SmdPin] N144773400 (<uTiL>cId1146<uTiL>.1) (7010.5 2648.0)" list(7010.500000 2648.000000) nil)@@@list("iris_chen" "2017/08/22 17:19:45" nil "P16C000357-PC" "5n-armani13.a00")@@@list("anson_lee" "2017/08/24 14:25:01" nil "P172000029-PC" "5n-armani13.a00.0824") | list("[Physical] BOTTOM" "280.Pad/Pad Direct Connect" "NOT_ALLOWED [(PWR_20)]" "ALL_ALLOWED" "" "DRC ERROR CLASS/BOTTOM" "[SmdPin] +DCIN_IN (<uTiL>cId1161<uTiL>.1) (7120.06 1466.0)" "[SmdPin] +DCIN_IN (<uTiL>cId1023<uTiL>.1) (7119.0 1481.37)" list(7120.060000 1466.000000) nil)@@@list("iris_chen" "2017/08/22 17:21:15" nil "P16C000357-PC" "5n-armani13.a00")@@@list("anson_lee" "2017/08/24 14:25:03" nil "P172000029-PC" "5n-armani13.a00.0824") | list("[Physical] BOTTOM" "275.Pad/Pad Direct Connect" "NOT_ALLOWED [DEFAULT]" "ALL_ALLOWED" "" "DRC ERROR CLASS/BOTTOM" "[SmdPin] DCIN_R (<uTiL>cId1023<uTiL>.2) (7119.0 1402.63)" "[SmdPin] DCIN_R (<uTiL>cId1162<uTiL>.1) (7120.06 1420.0)" list(7120.060000 1420.000000) nil)@@@list("iris_chen" "2017/08/22 17:19:24" nil "P16C000357-PC" "5n-armani13.a00")@@@list("anson_lee" "2017/08/24 14:25:00" nil "P172000029-PC" "5n-armani13.a00.0824") | list("[Physical] BOTTOM" "343.Pad/Pad Direct Connect" "NOT_ALLOWED [(GND_20)]" "ALL_ALLOWED" "" "DRC ERROR CLASS/BOTTOM" "[SmdPin] GND (<uTiL>cId539<uTiL>.33) (7505.0 1265.5)" "[ThruPin] GND (<uTiL>cId539<uTiL>.35) (7462.09 1308.41)" list(7462.090000 1308.410000) nil)@@@list("iris_chen" "2017/08/22 17:19:38" nil "P16C000357-PC" "5n-armani13.a00")@@@list("anson_lee" "2017/08/24 14:25:47" nil "P172000029-PC" "5n-armani13.a00.0824") | list("[Physical] BOTTOM" "341.Pad/Pad Direct Connect" "NOT_ALLOWED [(GND_20)]" "ALL_ALLOWED" "" "DRC ERROR CLASS/BOTTOM" "[SmdPin] GND (<uTiL>cId539<uTiL>.33) (7505.0 1265.5)" "[ThruPin] GND (<uTiL>cId539<uTiL>.37) (7462.09 1222.59)" list(7462.090000 1222.590000) nil)@@@list("iris_chen" "2017/08/22 17:19:38" nil "P16C000357-PC" "5n-armani13.a00")@@@list("anson_lee" "2017/08/24 14:25:45" nil "P172000029-PC" "5n-armani13.a00.0824") | list("[Physical] BOTTOM" "367.Pad/Pad Direct Connect" "NOT_ALLOWED [(PWR_25)]" "ALL_ALLOWED" "" "DRC ERROR CLASS/BOTTOM" "[SmdPin] N144773302 (<uTiL>cId1169<uTiL>.1) (7463.54 2087.0)" "[SmdPin] N144773302 (<uTiL>cId1147<uTiL>.1) (7464.0 2136.0)" list(7464.000000 2136.000000) nil)@@@list("iris_chen" "2017/08/22 17:21:20" nil "P16C000357-PC" "5n-armani13.a00")@@@list("anson_lee" "2017/08/24 14:26:03" nil "P172000029-PC" "5n-armani13.a00.0824") | list("[Physical] BOTTOM" "350.Pad/Pad Direct Connect" "NOT_ALLOWED [(GND_20)]" "ALL_ALLOWED" "" "DRC ERROR CLASS/BOTTOM" "[SmdPin] GND (<uTiL>cId539<uTiL>.33) (7505.0 1265.5)" "[ThruPin] GND (<uTiL>cId539<uTiL>.38) (7505.0 1265.5)" list(7505.000000 1265.500000) nil)@@@list("iris_chen" "2017/08/22 17:21:10" nil "P16C000357-PC" "5n-armani13.a00")@@@list("anson_lee" "2017/08/24 14:25:52" nil "P172000029-PC" "5n-armani13.a00.0824") | list("[Physical] BOTTOM" "344.Pad/Pad Direct Connect" "NOT_ALLOWED [(GND_20)]" "ALL_ALLOWED" "" "DRC ERROR CLASS/BOTTOM" "[SmdPin] GND (<uTiL>cId539<uTiL>.33) (7505.0 1265.5)" "[ThruPin] GND (<uTiL>cId539<uTiL>.34) (7547.91 1308.41)" list(7547.910000 1308.410000) nil)@@@list("iris_chen" "2017/08/22 17:19:37" nil "P16C000357-PC" "5n-armani13.a00")@@@list("anson_lee" "2017/08/24 14:25:47" nil "P172000029-PC" "5n-armani13.a00.0824") | list("[Physical] BOTTOM" "342.Pad/Pad Direct Connect" "NOT_ALLOWED [(GND_20)]" "ALL_ALLOWED" "" "DRC ERROR CLASS/BOTTOM" "[SmdPin] GND (<uTiL>cId539<uTiL>.33) (7505.0 1265.5)" "[ThruPin] GND (<uTiL>cId539<uTiL>.36) (7547.91 1222.59)" list(7547.910000 1222.590000) nil)@@@list("iris_chen" "2017/08/22 17:19:47" nil "P16C000357-PC" "5n-armani13.a00")@@@list("anson_lee" "2017/08/24 14:25:46" nil "P172000029-PC" "5n-armani13.a00.0824") | list("[Physical] BOTTOM" "340.Pad/Pad Direct Connect" "NOT_ALLOWED [(GND_20)]" "ALL_ALLOWED" "" "DRC ERROR CLASS/BOTTOM" "[SmdPin] GND (<uTiL>cId519<uTiL>.21) (7675.0 2585.0)" "[ThruPin] GND (<uTiL>cId519<uTiL>.23) (7655.31 2604.69)" list(7655.310000 2604.690000) nil)@@@list("iris_chen" "2017/08/22 17:19:23" nil "P16C000357-PC" "5n-armani13.a00")@@@list("anson_lee" "2017/08/24 14:25:45" nil "P172000029-PC" "5n-armani13.a00.0824") | list("[Physical] BOTTOM" "338.Pad/Pad Direct Connect" "NOT_ALLOWED [(GND_20)]" "ALL_ALLOWED" "" "DRC ERROR CLASS/BOTTOM" "[SmdPin] GND (<uTiL>cId519<uTiL>.21) (7675.0 2585.0)" "[ThruPin] GND (<uTiL>cId519<uTiL>.25) (7655.31 2565.31)" list(7655.310000 2565.310000) nil)@@@list("iris_chen" "2017/08/22 17:19:47" nil "P16C000357-PC" "5n-armani13.a00")@@@list("anson_lee" "2017/08/24 14:25:43" nil "P172000029-PC" "5n-armani13.a00.0824") | list("[Physical] BOTTOM" "339.Pad/Pad Direct Connect" "NOT_ALLOWED [(GND_20)]" "ALL_ALLOWED" "" "DRC ERROR CLASS/BOTTOM" "[SmdPin] GND (<uTiL>cId519<uTiL>.21) (7675.0 2585.0)" "[ThruPin] GND (<uTiL>cId519<uTiL>.22) (7694.69 2604.69)" list(7694.690000 2604.690000) nil)@@@list("iris_chen" "2017/08/22 17:19:23" nil "P16C000357-PC" "5n-armani13.a00")@@@list("anson_lee" "2017/08/24 14:25:44" nil "P172000029-PC" "5n-armani13.a00.0824") | list("[Physical] BOTTOM" "351.Pad/Pad Direct Connect" "NOT_ALLOWED [(GND_20)]" "ALL_ALLOWED" "" "DRC ERROR CLASS/BOTTOM" "[SmdPin] GND (<uTiL>cId519<uTiL>.21) (7675.0 2585.0)" "[ThruPin] GND (<uTiL>cId519<uTiL>.24) (7694.69 2565.31)" list(7694.690000 2565.310000) nil)@@@list("iris_chen" "2017/08/22 17:19:15" nil "P16C000357-PC" "5n-armani13.a00")@@@list("anson_lee" "2017/08/24 14:25:53" nil "P172000029-PC" "5n-armani13.a00.0824") | list("[Spacing-SameNet] BOTTOM" "207.Shape to Shape Same Net" "5 MIL [DEFAULT]" "0.6 MIL" "4.40 MIL" "DRC ERROR CLASS/BOTTOM" "[Bottom Shape] GND ((-191.01 273.9) (8699.38 4792.96))" "[Bottom Shape] GND ((7793.58 4409.0) (8021.0 4735.39))" list(7863.000000 4723.400000) nil)@@@list("iris_chen" "2017/08/22 17:18:49" nil "P16C000357-PC" "5n-armani13.a00")@@@nil | list("[Spacing] BOTTOM" "173.Shape to Route Keepout" "0 MIL [DEFAULT]" "0 MIL" "0.00 MIL" "DRC ERROR CLASS/BOTTOM" "[Shape] Route Keepout/All ((-211.01 253.9) (8719.38 4812.96))" "[Bottom Shape] GND ((7845.35 627.0) (8160.35 935.02))" list(7937.730000 634.110000) nil)@@@list("iris_chen" "2017/08/22 17:18:38" nil "P16C000357-PC" "5n-armani13.a00")@@@list("anson_lee" "2017/08/24 14:23:12" nil "P172000029-PC" "5n-armani13.a00.0824") | list("[Spacing] BOTTOM" "174.Shape to Route Keepin" "0 MIL [DEFAULT]" "0 MIL" "0.00 MIL" "DRC ERROR CLASS/BOTTOM" "[Shape] Route Keepin/All ((-191.01 273.9) (8699.38 4792.96))" "[Bottom Shape] GND ((7845.35 627.0) (8160.35 935.02))" list(8061.030000 631.160000) nil)@@@list("iris_chen" "2017/08/22 17:18:39" nil "P16C000357-PC" "5n-armani13.a00")@@@list("anson_lee" "2017/08/24 14:23:13" nil "P172000029-PC" "5n-armani13.a00.0824") | list("[Spacing] BOTTOM" "170.Shape to Route Keepin" "0 MIL [DEFAULT]" "0 MIL" "0.00 MIL" "DRC ERROR CLASS/BOTTOM" "[Shape] Route Keepin/All ((-191.01 273.9) (8699.38 4792.96))" "[Bottom Shape] GND ((-191.01 273.9) (8699.38 4792.96))" list(8699.380000 1168.460000) nil)@@@list("iris_chen" "2017/08/22 17:18:36" nil "P16C000357-PC" "5n-armani13.a00")@@@list("anson_lee" "2017/08/24 14:23:08" nil "P172000029-PC" "5n-armani13.a00.0824")
